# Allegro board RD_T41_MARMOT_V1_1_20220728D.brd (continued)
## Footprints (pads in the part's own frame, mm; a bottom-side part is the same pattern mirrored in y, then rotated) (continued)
QFP16_1D27
  rect 1.4x0.5 smd: 1(-4.6,4.445) 2(-4.6,3.175) 3(-4.6,1.905) 4(-4.6,0.635) 5(-4.6,-0.635) 6(-4.6,-1.905) 7(-4.6,-3.175) 8(-4.6,-4.445) 9(4.6,-4.445) 10(4.6,-3.175) 11(4.6,-1.905) 12(4.6,-0.635) 13(4.6,0.635) 14(4.6,1.905) 15(4.6,3.175) 16(4.6,4.445)
R0402
  rect 0.45x0.55 smd: 1(-0.52,0) 2(0.52,0)
R0603
  rect 0.76x0.76 smd: 1(-0.762,0) 2(0.762,0)
RJ45-LED-1A
  round 3.25 hole 3.25 unplated: (-6.35,5.135) (6.35,5.135)
  rect 1.27x1.27 hole 0.889: 1(3.58,7.675)
  round 1.27 hole 0.889: 2(2.56,9.45) 3(1.54,7.675) 4(0.52,9.45) 5(-0.5,7.675) 6(-1.52,9.45) 7(-2.54,7.675) 8(-3.56,9.45) 11(-6.86,14.27) 12(-4.57,14.27) 13(4.57,14.27) 14(6.86,14.27)
  round 2.286 hole 1.524: 9(-8.13,8.565) 10(8.13,8.565)
SIP2M_2D54
  rect 1.524x1.524 hole 0.889: 1(-1.27,0)
  round 1.524 hole 0.889: 2(1.27,0)
SMB
  rect 2x2.8 smd: 1(2.5,0) 2(-2.5,0)
SOD123
  rect 1.6x1.1 smd: 1(-1.8,0) 2(1.8,0)
SOD323
  rect 0.9x0.9 smd: 1(-1.05,0) 2(1.05,0)
SOP8_1D27_BM8563
  rect 0.4x1.5 smd: 1(-1.905,-2.7) 2(-0.635,-2.7) 3(0.635,-2.7) 4(1.905,-2.7) 5(1.905,2.7) 6(0.635,2.7) 7(-0.635,2.7) 8(-1.905,2.7)
SOT23
  rect 0.8x1.1 smd: 1(-0.95,-1.35) 2(0.95,-1.35) 3(0,1.35)
SOT23-3
  rect 0.8x1.1 smd: 1(0,1.4) 2(-0.95,-1.4) 3(0.95,-1.4)
SOT23-5
  rect 0.6x1.5 smd: 1(-0.95,-1.5) 2(0,-1.5) 3(0.95,-1.5) 4(0.95,1.5) 5(-0.95,1.5)
SOT23-6
  rect 1x0.4 smd: 1(-1.4,0.95) 2(-1.4,0) 3(-1.4,-0.95) 4(1.4,-0.95) 5(1.4,0) 6(1.4,0.95)
SW5_SMD
  oval 2.5x0.85 smd: 1(-3.7,-2.25) 3(-3.7,2.25) 4(3.7,2.25) 5(3.7,-2.25)
  oval 2.2x1 smd: 2(-4,0)
TEST_SMD
  round 1 smd: 1(0,0)
TEST_SMD_0D5
  round 0.5 smd: 1(0,0)
TFCARD
  round 1 hole 1 unplated: (-4.95,-10.6) (3.05,-10.6)
  rect 0.7x1.8 smd: 1(2.25,0.2) 2(1.15,0.2) 3(0.05,0.2) 4(-1.05,0.2) 5(-2.15,0.2) 6(-3.25,0.2) 7(-4.35,0.2) 8(-5.45,0.2) 9(-6.55,0.2)
  rect 1.6x1.4 smd: 10(-8,-0.6) 13(6.85,-0.6)
  rect 1.2x2.2 smd: 11(-7.75,-10.2) 12(7.75,-10.2)
TQFN16_0D5_SGM3124
  rect 0.7x0.23 smd: 1(-1.45,0.75) 2(-1.45,0.25) 3(-1.45,-0.25) 4(-1.45,-0.75) 9(1.45,-0.75) 10(1.45,-0.25) 11(1.45,0.25) 12(1.45,0.75)
  rect 0.23x0.7 smd: 5(-0.75,-1.45) 6(-0.25,-1.45) 7(0.25,-1.45) 8(0.75,-1.45) 13(0.75,1.45) 14(0.25,1.45) 15(-0.25,1.45) 16(-0.75,1.45)
  rect 1.5x1.5 smd: 17(0,0)
VR_3296W
  round 1.5 hole 0.8: 1(-2.5,0) 2(0,0) 3(2.5,0)
WSOP8_1D27
  rect 1.9x0.5 smd: 1(-3.645,1.905) 2(-3.645,0.635) 3(-3.645,-0.635) 4(-3.645,-1.905) 5(3.645,-1.905) 6(3.645,-0.635) 7(3.645,0.635) 8(3.645,1.905)

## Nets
12V_IN: F1.1 J2.3
AVDD33: C188.1 C189.1 R235.2 R236.1 U22.7(AVDD33_1)
AVDDL_REG: C98.1 C99.1 U6.R16(AVDDL_REG)
DVDD1V2OUT: C97.1 C100.1 U6.T14(DVDD1V2OUT)
GND: BAT1.2 BT1.2(-) C2.2 C3.2 C4.2 C5.2 C6.2 C8.2 C9.2 C10.2 C11.2 C12.2 C14.2 C16.2 C17.1 C18.2 C19.2 C21.2 C22.2 C23.2 C25.2 C26.2 C27.2 C28.2 C29.2 C30.2 C31.2 C32.2 C33.2 C34.2 C35.2 C36.2 C37.2 C38.2 C39.2 C40.2 C41.2 C42.2 C43.2 C44.2 C45.2 C46.2 C47.2 C48.2 C49.2 C51.2 C52.2 C53.2 C54.2 C55.2 C56.2 C57.1 C58.1 C59.1 C60.2 C61.2 C62.2 C63.2 C64.2 C67.2 C68.2 C69.1 C70.1 C71.2 C72.2 C73.2 C74.2 C75.2 C76.2 C77.2 C78.2 C79.2 C80.2 C81.2 C82.2 C83.2 C84.2 C85.2 C86.2 C87.2 C88.2 C89.2 C90.2 C91.2 C92.2 C93.2 C94.2 C95.2 C96.2 C97.2 C98.2 C99.2 C100.2 C101.2 C102.2 C103.2 C106.2 C107.2 C108.2 C109.2 C110.2 C111.2 C113.2 C114.2 C115.2 C116.2 C117.2 C118.2 C119.2 C120.2 C121.2 C122.2 C123.2 C124.2 C125.2 C126.2 C127.2 C128.2 C134.2 C135.2 C136.2 C137.2 C138.2 C139.2 C140.2 C141.2 C142.2 C143.2 C146.2 C147.2 C148.2 C149.2 C150.2 C151.2 C152.2 C153.1 C155.2 C156.2 C157.2 C158.2 C159.2 C160.2 C161.2 C162.2 C163.2 C165.2 C166.2 C167.2 C168.2 C169.2 C170.2 C171.2 C172.2 C173.2 C174.2 C175.1 C176.1 C177.1 C178.1 C179.1 C180.2 C181.2 C182.2 C183.2 C184.2 C185.2 C186.1 C187.2 C188.2 C189.2 C190.2 C191.1 C192.1 C193.1 C196.2 C197.2 C198.2 C199.2 C200.2 C201.2 C202.2 C203.2 C204.2 C205.2 C206.2 C207.2 C208.2 C209.1 C210.1 C211.2 C212.1 C214.2 C215.2 D1.1 D2.2(CATHODE) D3.1(ANODE) D4.1(ANODE) D5.1(ANODE) D6.1(ANODE) D7.1(ANODE) D8.1(ANODE) D9.1(ANODE) D10.1(ANODE) D11.1(ANODE) D12.1(ANODE) D13.1(ANODE) D14.1(ANODE) D15.1(ANODE) D16.2 H1.1(A) H2.1(A) H3.1(A) H4.1(A) H5.1(A) H6.1(A) J1.1 J1.2 J7.5(GND1) J7.6(GND2) J7.7(GND3) J7.8(GND4) J7.9(GND5) J7.10(GND6) J7.11(GND7) J9.3(S1) J9.4(S2) J10.3(S1) J10.4(S2) J11.7 J11.10 J11.15 J11.20 J11.27 J11.29 J11.37(S1) J11.38(S2) J12.1 J12.4 J12.7 J12.10 J12.13 J12.16 J12.21 J12.23 J12.27 J12.31(S1) J12.32(S2) J13.3(S1) J13.4(S2) J14.3(S1) J14.4(S2) J15.3(S1) J15.4(S2) J16.6(VSS2) J16.10(GND_2) J16.11(GND_1) J16.12(PAD1) J16.13(PAD2) J17.1 J17.4 J17.8 J17.9 J17.19 J17.32 J17.39 J17.41(S1) J17.42(S2) J18.9(S1) J18.10(S2) J19.9(SH1) J19.10(SH2) J19.12(CON_PIN[11]) J19.14(CON_PIN[13]) J22.1(GND_1) J22.23(DB0) J22.24(DB1) J22.25(DB2) J22.26(DB3) J22.27(DB4) J22.28(DB5) J22.29(DB6) J22.30(DB7) J22.31(DB8) J22.32(DB9) J22.42(GND_2) J22.50(GND_3) J22.51(S1) J22.52(S2) J23.4 J23.13 J23.14 J26.2 J26.5(S1) J26.6(S2) R3.1 R8.1 R9.1 R14.1 R15.1 R20.1 R21.1 R22.1 R29.1 R38.1 R39.3 R40.1 R41.1 R42.1 R59.2 R61.2 R62.2 R89.2 R98.1 R100.2 R102.2 R143.1 R146.1 R149.1 R150.1 R162.1 R170.1 R175.1 R176.2 R177.2 R186.2 R199.1 R217.2 R223.2 R225.1 R226.1 R230.2 R233.2 R248.2 R255.2 R267.1 R276.2 R282.1 R300.1 R308.1 R310.2 R315.2 R317.2 SW1.2 SW1.3 SW1.4 SW2.1 SW2.2 SW2.5 SW4.1 SW4.2 SW4.5 SW5.2 T2.1 T2.2 T2.3 T2.4 T2.5 T2.6 T2.7 T2.8 T2.9 T3.1 T3.2 T3.3 T3.4 T3.5 T3.6 T3.7 T3.8 T3.9 T6.1 T6.2 T6.3 T6.4 T6.5 T6.6 T6.7 T6.8 T6.9 T7.1 T7.2 T7.3 T7.4 T7.5 T7.6 T7.7 T7.8 T7.9 U1.2(GND) U2.2(GND) U3.2(GND) U4.2(GND) U5.2(GND) U6.C9(DDRPLL_VSSA) U6.G5(PLL_AVSS) U6.G6(VSS1) U6.G7(VSS2) U6.G8(VSS3) U6.G9(VSS4) U6.G10(VSS5) U6.G11(VSS6) U6.G12(VSS7) U6.G13(VSS8) U6.J6(VSS9) U6.J7(VSS10) U6.J8(VSS11) U6.J9(VSS12) U6.J10(VSS13) U6.J11(VSS14) U6.J12(VSS15) U6.K6(VSS16) U6.K7(VSS17) U6.K8(VSS18) U6.K9(VSS19) U6.K10(VSS20) U6.K11(VSS21) U6.K12(VSS22) U6.L6(VSS23) U6.L7(VSS24) U6.L8(VSS25) U6.L9(VSS26) U6.L10(VSS27) U6.L11(VSS28) U6.L12(VSS29) U6.M7(VSS30) U6.M8(VSS31) U6.M9(VSS32) U6.M10(VSS33) U6.M11(VSS34) U6.M12(VSS35) U6.M13(VSS36) U6.N5(CSI_VSSA) U6.N12(VSS37) U6.N13(SADC_AGND) U6.P4(CODEC_AVSS) U7.4(GND) U8.1(GND) U9.2(GND) U10.2(GND) U11.7(GND) U12.A6(VSS_1) U12.C4(VSSQ_1) U12.E7(VSS_2) U12.G5(VSS_3) U12.H10(VSS_4) U12.J5(VSS_5) U12.K8(VSS_6) U12.N2(VSSQ_2) U12.N5(VSSQ_3) U12.P4(VSSQ_4) U12.P6(VSSQ_5) U13.5(GND1) U13.6(GND2) U13.7(GND3) U13.8(GND4) U14.5(GND1) U14.6(GND2) U14.7(GND3) U14.8(GND4) U15.5(GND1) U15.6(GND2) U15.7(GND3) U15.8(GND4) U16.5(GND1) U16.6(GND2) U16.7(GND3) U16.8(GND4) U17.2(AVSS1) U17.13(DVSS1) U17.25(DVSS2) U17.30(AVSS2) U17.37(E-PAD) U18.2(GND) U19.7(GND) U20.2(GND) U21.6(GND5) U21.12(MGNDB) U21.18(MGNDA) U21.22(GNDD) U21.33(E-PAD) U22.33(GND) U24.7(PGND) U24.14(GND) U24.17(POWER_PAD) U25.2(GND) U26.2(GND) U27.4(GND) U28.4(GND) Y2.2 Y2.4 Y3.2 Y3.4
VBAT: BAT1.1 C205.1 C211.1 R295.2 R296.1 R303.2 U25.1(VIN) U27.8(VDD)
VBUS_5V: C81.1 C82.1 D4.2(CATHODE) FB8.1 J7.1(VBUS) J8.2
VCC_1V8: C24.1 C27.1 C204.1 J6.1 L5.2 Q1.1(BASE) Q3.2(SOURCE) R13.2 R30.1 R33.1 R36.1 R37.2 U8.3(VCC)
VCC_3V3: C13.1 C18.1 C110.1 C159.1 C160.1 C161.1 C162.1 C163.1 C164.1 C180.1 C181.1 D21.1(ANODE) D22.1(ANODE) FB11.1 FB12.1 FB13.2 FB14.2 FB15.2 FB16.2 J3.1 J17.2 J17.3 J17.5 J17.6 J17.7 J26.1 L2.2 Q2.2(SOURCE) R7.2 R24.2 R73.2 R99.1 R107.2 R128.1 R163.2 R192.2 R198.1 R201.2 R204.1 R215.1 R222.1 R227.1 R232.1 R234.1 R236.2 R249.2 R251.1 R252.1 R257.2 R281.1 R288.2 R289.1 R290.1 R297.1 R301.2 R304.1 R305.2 R306.2 R307.2 R314.1 R316.1 U10.1(VIN) U22.14(DVDD33_1)
VCC_5V: C7.1 C8.1 C9.1 C10.1 C11.1 C14.1 C21.1 C25.1 C80.1 C151.1 C202.1 C203.1 J8.1 J23.1 J23.2 L1.2 R2.1 R4.1 R5.1 R10.1 R11.1 R25.2 R106.2 R122.2 R127.1 R185.2 R189.2 R202.2 R205.2 R207.2 R260.2 TP1.1 U2.4(IN) U3.4(IN) U4.4(IN) U5.4(IN) U9.3(VIN) U18.1(VIN)
VCC_12V: C2.1 C3.1 C4.1 C5.1 D1.2 F1.2 R1.1 TP2.1 U1.5(VIN)
VCC_BAT: BT1.1(+) R35.2
VCC_DDR: C20.1 C23.1 J5.1 L4.2 R12.2
VCCQ_3V3: C115.1 C116.1 FB12.2 R133.1 R134.1 R135.1 R136.1 R137.1 R138.1 R139.1 R140.1 R141.1 R142.2 U12.C6(VCCQ_5) U12.M4(VCCQ_1) U12.N4(VCCQ_2) U12.P3(VCCQ_3) U12.P5(VCCQ_4)
VDD5: C168.1 R207.1 U21.4(VDD5)
VDD_RTC: C59.2 R294.1 U6.L15(VDD_RTC)
VDDIO18: C192.2 R28.1 U6.N11(VDDIO18_1)
VDDIO18_DVP: C95.1 R44.2 U6.K2(VDDIO18_2)
VDDIO33_1: C101.1 R64.1 U6.C4(VDDIO2)
VDDIO33_2: C102.1 C103.1 R63.1 U6.J14(VDDIO1_2) U6.P9(VDDIO1_1)
VDDIO_RTC: C191.2 R323.1 U6.L17(VDDIO_RTC)
VDDMEM: C40.1 C41.1 C42.1 C43.1 C44.1 R17.2 U6.E6(VDDMEM1) U6.E7(VDDMEM2) U6.E8(VDDMEM3) U6.E9(VDDMEM4) U6.E10(VDDMEM5) U6.E11(VDDMEM6) U6.E12(VDDMEM7)
VDDMSC0: C165.1 C166.1 J16.4(VDD) Q2.3(DRAIN) R193.1 R194.1 R195.1 R196.1 R197.1 R199.2
ADC0: C87.1 R35.1 R40.2 TP14.1 U6.P15(SADC_VIN0)
ADC1: C88.1 R36.2 R41.2 TP17.1 U6.R17(SADC_VIN1)
ADC2: C89.1 Q1.2(EMITTER) R42.2 TP15.1 U6.P16(SADC_VIN2)
ADC3: C90.1 R39.2 TP16.1 U6.N15(SADC_VIN3)
ADC_AVDD: C71.1 C72.1 FB7.2 U6.N16(SADC_VREFP) U6.N17(SADC_AVDD)
AK7755_AVDD: C139.1 C140.1 C141.1 C157.1 FB17.2 R183.2 R191.2 U17.21(AVDD1) U17.36(AVDD3) U20.1(VIN)
AK7755_AVDD2: C137.1 C138.1 FB17.1 U17.29(AVDD2)
AK7755_AVDRV: C134.1 U17.24(DVDD/AVDRV)
AK7755_IOVDD: C142.1 C143.1 R163.1 R166.2 R168.1 R169.1 R171.2 R172.2 R174.2 U17.12(TVDD)
AK7755_LDOE: R166.1 U17.23(LDOE)
AK7755_LIN: C130.1 TP50.1
AK7755_PDN: R83.1 R171.1 R173.1
AK7755_VCOM: C135.1 U17.1(VCOM)
BOOTSEL0: D23.2(CATHODE) R297.2 SW4.3 SW4.4 U6.A9(BOOT_SEL0_PC00)
BOOTSEL1: D24.1(ANODE) R300.2 SW5.3 SW5.4 U6.B9(BOOT_SEL1_PC01)
BT656_D0_PD00: J23.5 R254.2
BT656_D1_PD01: J23.6 R256.2
BT656_D2_PD02: J23.7 R259.2
BT656_D3_PD03: J23.8 R263.2
BT656_D4_PD04: J23.9 R264.2
BT656_D5_PD05: J23.10 R268.2
BT656_D6_PD06: J23.11 R270.2
BT656_D7_PD07: J23.12 R272.2
BT656_PCLK_PD08: J23.3 R274.2
CLK_CTRL: R232.2 R233.1 U22.12(RXD[3]/CLK_CTL)
CLKO: TP54.1 U17.9(CLKO)
CODEC_AVDD: C61.1 C62.1 FB6.2 U6.R1(CODEC_AVDD)
CORE_0V8: C29.1 C30.1 C31.1 C32.1 C33.1 C34.1 C35.1 C36.1 C37.1 C38.1 C39.1 J4.2 TP4.1 U6.H5(VDD1) U6.H6(VDD2) U6.H7(VDD3) U6.H8(VDD4) U6.H9(VDD5) U6.H10(VDD6) U6.H11(VDD7) U6.H12(VDD8) U6.H13(VDD9) U6.J5(VDD10) U6.J13(VDD11) U6.K5(VDD12) U6.K13(VDD13) U6.L5(VDD14) U6.M5(VDD15) U6.M6(VDD16) U6.N6(VDD17) U6.N7(VDD18) U6.N8(VDD19) U6.N9(VDD20) U6.N10(VDD21)
CSI_CLKN_DVP_D4: R118.1 R119.1 TP39.1 U6.M2(CSI_CLKN_DVP_D4)
CSI_CLKP_DVP_D5: R116.1 R117.1 TP38.1 U6.L3(CSI_CLKP_DVP_D5)
CSI_DATAN0_DVP_D0: R110.1 R111.1 TP34.1 U6.L2(CSI_DATAN0_DVP_D0)
CSI_DATAN1_DVP_D2: R114.1 R115.1 TP37.1 U6.N1(CSI_DATAN1_DVP_D2)
CSI_DATAP0_DVP_D1: R108.1 R109.1 TP31.1 U6.L1(CSI_DATAP0_DVP_D1)
CSI_DATAP1_DVP_D3: R112.1 R113.1 TP36.1 U6.M3(CSI_DATAP1_DVP_D3)
CSI_VCC08: C91.1 C92.1 FB9.1 U6.N2(CSI_VCCA08)
CSI_VCC18: C93.1 C94.1 FB10.1 U6.K3(CSI_VCCA18)
D_RX: J26.3 R292.1
D_TX: J26.4 R293.1
DC_12V: J1.3 J2.2
DDR_VREF: C50.2 C54.1 R19.1 R22.2 U6.E5(DDR_VREF)
DDRPLL_VCCA: C51.1 C52.1 FB1.2 U6.B8(DDRPLL_VCCA)
DDRVDD: C45.1 C46.1 C47.1 C48.1 C49.1 C50.1 C53.1 R18.2 R19.2 U6.F5(DDRVDD1) U6.F6(DDRVDD2) U6.F7(DDRVDD3) U6.F8(DDRVDD4) U6.F9(DDRVDD5) U6.F10(DDRVDD6) U6.F11(DDRVDD7) U6.F12(DDRVDD8)
DMIC_CLK_PB28: R144.2 R147.2 R153.2 R154.2 R157.2
DMIC_DAT0_PB29: R145.2 R148.2 R321.2
DMIC_DAT1_PB30: R155.2 R158.2 R322.2
DRV_VBUS: R38.2 R55.2 U9.4(EN)
DVP_3V3: J11.1 J11.2 R107.1
DVP_5V: J11.34 J11.35 J11.36 R122.1
DVP_D0: J11.11 R111.2
DVP_D1: J11.12 R109.2
DVP_D2: J11.13 R115.2
DVP_D3: J11.14 R113.2
DVP_D4: J11.16 R119.2
DVP_D5: J11.17 R117.2
DVP_D6: J11.18 U6.H2(SD0_DVP_D6_PA06)
DVP_D7: J11.19 U6.H3(SD1_DVP_D7_PA07)
DVP_D8: J11.21 U6.G1(SD2_DVP_D8_PA08)
DVP_D9: J11.22 U6.G2(SD3_DVP_D9_PA09)
DVP_D10: J11.23 U6.G3(SD4_DVP_D10_PA10)
DVP_D11: J11.24 U6.F2(SD5_DVP_D11_PA11)
DVP_HSYNC: J11.8 TP33.1 U6.J2(CS2_DVP_HSYNC_PA16)
DVP_MCLK_PA15: J11.28 R126.2 TP30.1
DVP_PCLK: J11.26 TP32.1 U6.F3(SA0_DVP_PCLK__PA14)
DVP_VSYNC: J11.9 TP35.1 U6.J3(RD_DVP_VSYNC_PA17)
E_MICBIAS_2V5: C156.1 R182.2 R184.2 U20.5(VOUT)
EC_CLK: R45.2 R65.2 U6.A1(MSC1_CLK_PC02)
EC_CMD: R66.2 R309.1 U6.C3(MSC1_CMD_PC03)
EC_D0: R69.2 R311.1 U6.B2(MSC1_D0_PC04)
EC_D1: R70.2 R318.1 U6.A2(MSC1_D1_PC05)
EC_D2: R71.2 R319.1 U6.C2(MSC1_D2_PC06)
EC_D3: R74.2 R320.1 U6.B1(MSC1_D3_PC07)
EFUSE_AVDD: R324.1 U6.D4(EFUSE_AVDD)
EFUSE_AVDD18: Q3.3(DRAIN) R282.2 R324.2
EFUSE_EN: Q3.1(GATE) R79.1 R281.2
EMMC_3V3: C114.1 C117.1 FB11.2 U12.E6(VCC_1) U12.F5(VCC_2) U12.J10(VCC_3) U12.K9(VCC_4)
EMMC_CLK: C119.1 R65.1 U12.M6(CLK)
EMMC_CMD: R66.1 R141.2 U12.M5(CMD)
EMMC_D0: R69.1 R133.2 U12.A3(DAT0)
EMMC_D1: R70.1 R134.2 U12.A4(DAT1)
EMMC_D2: R71.1 R135.2 U12.A5(DAT2)
EMMC_D3: R74.1 R136.2 U12.B2(DAT3)
EMMC_D4: R137.2 U12.B3(DAT4)
EMMC_D5: R138.2 U12.B4(DAT5)
EMMC_D6: R139.2 U12.B5(DAT6)
EMMC_D7: R140.2 U12.B6(DAT7)
EMMC_DS: TP47.1 U12.H5(DS)
EMMC_RST: C118.1 R76.2 R142.1 U12.K5(RSTN)
EMMC_VDDI: C120.1 U12.C2(VDDI)
EN_DLDO: R60.1 R61.1 U6.U15(EN_DLDO)
EXCLKI: C69.2 R31.2 U6.C1(EXCLK_XIN) Y2.1
EXCLKO: R31.1 R32.2 U6.D2(EXCLK_XOUT)
GMAC_MDC: R49.2 U22.22(MDC)
GMAC_MDIO: R51.2 R215.2 U22.23(MDIO)
GMAC_NRST_PB28: R156.1 R287.2 R298.1
GMAC_PHY_CLK: R47.2 U22.31(XTAL_IN)
GMAC_RXD0: R220.1 U6.U13(GMAC_RXD0_PWM6_PB15)
GMAC_RXD1: R221.1 R222.2 R223.1 U6.R12(GMAC_RXD1_PWM7_PB16)
GMAC_RXDV: R218.1 U6.U9(GMAC_RXDV_PWM3_PB09)
GMAC_TXCLK: R212.1 U6.T12(GMAC_TXCLK_PB06)
GMAC_TXD0: R52.2 U22.16(TXD[0])
GMAC_TXD1: R53.2 U22.17(TXD[1])
GMAC_TXEN: R48.2 U22.20(TXEN)
HPOUTL: C112.2 U6.T1(HPOUTL)
I2C0_MIPI_DVP_SCK: J11.3 J12.20 TP41.1 U6.J4(SD7_SMB0_SCK_PA13)
I2C0_MIPI_DVP_SDA: J11.6 J12.19 TP40.1 U6.J1(SD6_SMB0_SDA_PA12)
I2C1_SCK_CODEC: R88.1 R169.2 U17.18(SCLK/SCL)
I2C1_SCK_RTC: R307.1 U6.C10(SMB1_SCK_UART3_RXD_PB26) U27.6(SCL)
I2C1_SDA_CODEC: R86.1 R168.2 U17.17(SO/SDA)
I2C1_SDA_RTC: R306.1 U6.C11(SMB1_SDA_UART3_TXD_PB25) U27.5(SDA)
I2C2_SID: R174.1 R175.2 U17.20(CSN/CAD/MATSEL)
I2S_DAC_BCLK: R160.1 U6.B4(SSI_SLV_CLK_I2S_DAC_BCLK_PC15)
I2S_DAC_BCLK_PC15: R160.2 U17.8(BICK)
I2S_DAC_LRCK: R159.1 U6.A3(SSI_SLV_CE0_I2S_DAC_LRCK_PC16)
I2S_DAC_LRCK_PC16: R159.2 U17.7(LRCK)
I2S_DAC_MCLK: R77.1 U17.11(XTI)
I2S_SDTI: R161.1 U6.B5(SSI_SLV_DR_I2S_SDTI_PC18)
I2S_SDTI_PC18: R161.2 U17.16(SDOUT1/EEST)
I2S_SDTO: R164.1 U6.B3(SSI_SLV_DT_I2S_SDTO_PC17)
I2S_SDTO_PC17: R164.2 U17.4(SDIN2/JX1)
I_MICBIAS_2V5: C109.1 R93.2 U10.5(VOUT)
IM0: J22.12(IM0) R249.1
IM1: J22.11(IM1) R255.1
IM2: J22.10(IM2) R248.1
INN1: C131.2 U17.33(IN2/INN1/DMCLK1)
INN2: C133.2 U17.31(IN4/INN2/DMCLK2)
INP1: C129.2 U17.34(IN1/INP1/DMDAT1)
INP2: C132.2 U17.32(IN3/INP2/DMDAT2)
IRCUT_IN1: TP62.1 U21.2(IN1)
IRCUT_IN2: TP63.1 U21.3(IN2)
KEY1_PB19: R288.1 SW2.3 SW2.4 TP20.1 U6.D16(MSC1_CMD_PB19)
LED0: R246.1 U6.R13(LED0)
LED1: R299.1 U6.R15(LED1)
LED2: TP65.1 U21.21(LED2)
LED11: TP64.1 U21.20(LED1)
LIN: C130.2 U17.35(LIN)
LR1: R129.2 R143.2 U13.2(L/R)
LR2: R130.2 R146.2 U14.2(L/R)
LR3: R131.2 R149.2 U15.2(L/R)
LR4: R132.2 R150.2 U16.2(L/R)
M_F_A+: J18.7 U21.14(OUTB2)
M_F_A-: J18.8 U21.16(OUTB1)
M_F_B+: J18.1 U21.17(OUTA2)
M_F_B-: J18.2 U21.19(OUTA1)
M_OSCIN: R209.2 U21.24(OSCIN)
M_OSCOUT: R211.2 U21.23(OSCOUT)
M_RSTB: C167.1 R72.2 R204.2 U21.1(RSTB)
M_VD_FZ: R75.2 U21.30(VD_FZ)
M_Z_A+: J18.5 U21.8(OUTD2)
M_Z_A-: J18.6 U21.10(OUTD1)
M_Z_B+: J18.4 U21.11(OUTC2)
M_Z_B-: J18.3 U21.13(OUTC1)
MDI_RN: R219.2 R244.2 U23.1(TD+/RD+)
MDI_RP: R216.2 R242.2 U23.3(TD-/RD-)
MDI_TN: R214.2 R240.2 U23.6(RD+/TD+)
MDI_TP: R213.2 R238.2 U23.8(RD-/TD-)
MDVDD: C173.1 C174.1 R201.1 U21.25(DVDD)
MICBIAS: C85.1 C86.1 R94.2 U6.P3(MICBIAS)
MICN1: C131.1 C144.1 D11.2(CATHODE) J13.1 R176.1 R178.1
MICN2: C133.1 C145.1 D13.2(CATHODE) J14.1 R177.1 R179.1
MICNL: C66.2 C104.1 D7.2(CATHODE) J9.1 R90.1 R313.2
MICP1: C129.1 C144.2 D10.2(CATHODE) J13.2 R178.2 R180.2
MICP2: C132.1 C145.2 D12.2(CATHODE) J14.2 R179.2 R181.2
MICPL: C65.2 C104.2 D6.2(CATHODE) J9.2 R91.2 R97.2
MINNL: C66.1 U6.P2(MICNL)
MINPL: C65.1 U6.N3(MICPL)
MIPI1_2LANE_3V3: J12.30 R128.2
MIPI1_2LANE_5V: J12.28 J12.29 R127.2
MIPI_DVP_IRCUTN_PB18: J11.31 J12.25 TP19.1 U6.E17(MSC1_D1_PB18)
MIPI_DVP_IRCUTP_PB17: J11.32 J12.24 TP18.1 U6.E16(MSC1_D0_PB17)
MIPI_DVP_MCLK: R50.1 R125.1 R126.1 TP42.1
MIPI_DVP_PWDN_PA19: J11.25 J12.26 R229.1 TP44.1
MIPI_DVP_RESET: J11.33 J12.18 TP43.1 U6.E3(SA2_PA18)
MIPI_MCLK_PA15: J12.22 R125.2 TP46.1
MIPI_RX_2LANE_CLKN0: J12.2 R118.2
MIPI_RX_2LANE_CLKP0: J12.3 R116.2
MIPI_RX_2LANE_DN0: J12.5 R110.2
MIPI_RX_2LANE_DN1: J12.8 R114.2
MIPI_RX_2LANE_DP0: J12.6 R108.2
MIPI_RX_2LANE_DP1: J12.9 R112.2
MSC0_CLK_PB04: J16.5(CLK) R43.2 TP61.1
MSC0_CMD_PB05: J16.3(CMD) R197.2 TP60.1 U6.G17(MSC0_CMD_PB05)
MSC0_D0_PB00: J16.7(DAT0) R193.2 TP56.1 U6.H16(MSC0_D0_PB00)
MSC0_D1_PB01: J16.8(DAT1) R194.2 TP57.1 U6.J15(MSC0_D1_PB01)
MSC0_D2_PB02: J16.1(DAT2) R195.2 TP58.1 U6.G15(MSC0_D2_PB02)
MSC0_D3_PB03: J16.2(DAT3) R196.2 TP59.1 U6.G16(MSC0_D3_PB03)
MVCCA: C169.1 C170.1 R202.1 U21.15(MVCCA)
MVCCB: C171.1 C172.1 R205.1 U21.9(MVCCB)
OSC32_XI: C57.2 R23.2 U6.M16(OSC32_XI) Y1.2
OSC32_XO: C58.2 R23.1 U6.M15(OSC32_XO) Y1.1
OUT2_R: TP48.1 U17.26(OUT2)
OUT3_MIXER: TP49.1 U17.27(OUT3)
OUTE1: TP66.1 U21.7(OUTE1)
OUTE2: TP69.1 U21.5(OUTE2)
PHY_ACTA: R224.2 R245.2 R246.2
PHY_LED0: R245.1 R314.2 R315.1 U22.24(LED0/PHYAD[0])
PHY_LED1: R247.1 R316.2 R317.1 U22.25(LED1/PHYAD[1])
PHY_LINKA: R231.2 R247.2 R299.2
PHY_NRST: C96.1 R56.1 R287.1 U6.T13(PHY_RST)
PLL_AVDD18: C55.1 C56.1 FB3.2 U6.D3(PLL_AVDD)
POR_CTRL: R29.2 R30.2 U6.K16(POR_CTL)
PPRST_N: R34.2 U6.L16(PPRST_) U8.2(RESET)
PULSE1: TP67.1 U21.31(PULSE1)
PULSE2: TP68.1 U21.32(PULSE2)
PWRON: TP9.1 U6.K15(PWRON)
RD_N: R244.1 U6.U17(RD_N)
RD_P: R242.1 U6.T17(RD_P)
RMII_MDCK: R49.1 U6.R10(GMAC_MDCK_SMB2_SDA_PB10)
RMII_MDIO: R51.1 U6.T10(GMAC_MDIO_SMB2_SCK_PB11)
RMII_PHY_CLK: R47.1 U6.T9(GMAC_PHY_CLK_PB07)
RMII_TX0: R52.1 U6.R11(GMAC_TXD0_PWM4_PB13)
RMII_TX1: R53.1 U6.T11(GMAC_TXD1_PWM5_PB14)
RMII_TXEN: R48.1 U6.U11(GMAC_TXEN_PWM2_PB08)
RST_OUT: TP7.1 U6.J16(RST_OUT)
RTC_0V8: C208.1 R294.2 TP70.1 U26.5(VOUT)
RTC_1V8: C206.1 C207.1 R285.1 R323.2 U25.5(VOUT) U26.1(VIN)
RTC_IRQ_N: R46.1 R68.2 R305.1 U27.3(INT)
RX+: J19.3(CON_PIN[2]) U23.14(TX-/RX-)
RX-: J19.6(CON_PIN[5]) U23.16(TX+/RX+)
RX_DV: R57.1 U6.P14(RX_DV)
RX_N1: R219.1 U22.6(TRXN1)
RX_P1: R216.1 U22.5(TRXP1)
RXD3: R58.1 R59.1 U6.R14(RXD3)
RXDV: R227.2 R230.1 U22.8(RXDV)
SD0_CD_N_PB27: J16.9(CD) R54.1 R192.1 R237.1
SD_CLK: R43.1 U6.H15(MSC0_CLK_PB04)
SD_PWR_EN_N: R239.1 TP21.1 U6.E15(MSC1_CLK_TCK_PB20)
SDIN1: R162.2 U17.5(SDIN1/JX0)
SDIO_WIFI_CLK_PC02: J17.24 R45.1
SDIO_WIFI_CMD_PC03: J17.34 R309.2
SDIO_WIFI_D0_PC04: J17.23 R311.2
SDIO_WIFI_D1_PC05: J17.35 R318.2
SDIO_WIFI_D2_PC06: J17.33 R319.2
SDIO_WIFI_D3_PC07: J17.36 R320.2
SDIO_WIFI_EN_PC09: J17.16 U6.C6(SMB2_SCK_PC09)
SDOUT2: TP51.1 U17.15(SDOUT2/JX3/MAT0)
SDOUT3: TP52.1 U17.14(SDOUT3/JX2/MAT1)
SFC1_CE: R123.1 R124.1 U6.R7(SFC1_CE_PA29)
SFC1_CLK: R120.1 R121.1 U6.T8(SFC1_CLK_PA22)
SFC1_CS_N: R78.1 R124.2 U28.1(C\S\)
SFC1_DR_IO1: R67.1 R87.1 U6.T7(SFC1_DR_IO1_PA21)
SFC1_DT_IO0: R82.1 R85.1 U6.R8(SFC1_DT_IO0_PA20)
SFC1_HD_IO3: R75.1 R165.1 U6.R9(SFC1_HOLD_IO3_PA31)
SFC1_SCLK: R121.2 U28.6(SCLK)
SFC1_SIO0: R85.2 U28.5(SI/SIO0)
SFC1_SIO1: R87.2 U28.2(SO/SIO1)
SFC1_SIO2: R167.2 U28.3(W\P\/SIO2)
SFC1_SIO3: R165.2 U28.7(R\E\S\E\T\/SIO3)
SFC1_WP_IO2: R72.1 R167.1 U6.U7(SFC1_WP_IO2_PA30)
SFC_CS_N: R26.1 U6.T4(SFC0_CE_PA28) U7.1(C\S\)
SFC_SCLK: U6.R6(SFC0_CLK_PA27) U7.6(SCLK)
SFC_SIO0: U6.U5(SFC0_DT_IO0_PA23) U7.5(SI/SIO0)
SFC_SIO1: U6.R5(SFC0_DR_IO1_PA24) U7.2(SO/SIO1)
SFC_SIO2: U6.T5(SFC0_WP_IO2_PA26) U7.3(W\P\/SIO2)
SFC_SIO3: U6.T6(SFC0_HOLD_IO3_PA25) U7.7(R\E\S\E\T\/SIO3)
SLCD_BLEN: R81.1 R276.1 U24.15(EN1) U24.16(EN2)
SLCD_BT656_D0: R253.1 R254.1 U6.A15(SLCD_D0_UART3_TXD_PD00)
SLCD_BT656_D1: R250.1 R256.1 U6.B15(SLCD_D1_UART3_RXD_PD01)
SLCD_BT656_D2: R258.1 R259.1 U6.A16(SLCD_D2_UART4_TXD_PD02)
SLCD_BT656_D3: R261.1 R263.1 U6.C15(SLCD_D3_UART4_RXD_PD03)
SLCD_BT656_D4: R262.1 R264.1 U6.A17(SLCD_D4_UART5_TXD_PD04)
SLCD_BT656_D5: R266.1 R268.1 U6.B16(SLCD_D5_UART5_RXD_PD05)
SLCD_BT656_D6: R269.1 R270.1 U6.B17(SLCD_D6_SMB1_SDA_PD06)
SLCD_BT656_D7: R271.1 R272.1 U6.C16(SLCD_D7_SMB1_SCK_PD07)
SLCD_CS: R277.1 TP27.1 U6.B13(SLCD_CS_PWM5_PD10)
SLCD_CS_PD10: J22.14(CS) R277.2
SLCD_D0_PD00: J22.33(DB10) R253.2
SLCD_D1_PD01: J22.34(DB11) R250.2
SLCD_D2_PD02: J22.35(DB12) R258.2
SLCD_D3_PD03: J22.36(DB13) R261.2
SLCD_D4_PD04: J22.37(DB14) R262.2
SLCD_D5_PD05: J22.38(DB15) R266.2
SLCD_D6_PD06: J22.39(DB16) R269.2
SLCD_D7_PD07: J22.40(DB17) R271.2
SLCD_DC: R278.1 TP28.1 U6.C13(SLCD_DC_PWM6_PD11)
SLCD_DC_PD11: J22.15(RS_SPI-RS) R278.2
SLCD_IOVDD: C198.1 C200.1 J22.6(IOVCC_1) J22.7(IOVCC_2) R251.2
SLCD_LEDA: C201.1 J22.43(LEDA) U24.8(VOUT)
SLCD_LEDK: J22.44(LEDK1) J22.45(LEDK2) J22.46(LEDK3) J22.47(LEDK4) J22.48(LEDK5) J22.49(LEDK6) R265.2 U24.5(D2) U24.6(D1)
SLCD_RDY: R279.1 TP29.1 U6.C14(SLCD_RDY_PWM7_PD12)
SLCD_RDY_PD12: J22.17(RD) R257.1 R279.2
SLCD_RST_PD09: J22.13(RESET) R275.2
SLCD_TE: R275.1 TP26.1 U6.A13(SLCD_TE_PWM4_PD09)
SLCD_VCI: C197.1 C199.1 J22.8(VCI_1) J22.9(VCI_2) R252.2
SLCD_WR_BT656_PCLK: R273.1 R274.1 U6.B14(SLCD_WR_PD08)
SLCD_WR_PD08: J22.16(WR_SPI-SCL) R273.2
SOC_0V8: C15.2 C16.1 C17.2 J4.1 L3.2 R6.2 R325.1 R330.2
SOC_1V8: J6.2 R27.2 R28.2 R44.1 R80.1 R84.1 R326.1 R328.1 R329.1 R331.2 TP6.1
SOC_3V3: J3.2 R16.1 R56.2 R57.2 R58.2 R60.2 R63.2 R64.2 R327.1 TP3.1
SOC_DDR: J5.2 R17.1 R18.1 TP5.1
SPEAK_EN_PB31: R103.1 R187.1 U6.B10(GPIO_PB31)
SPI1_CLK: R120.2 R206.1
SPI1_CLK_PA22: R206.2 U21.26(SCK)
SPI1_CS: R123.2 R208.1
SPI1_CS_PA29: R208.2 U21.27(CS)
SPI1_DR: R67.2 R203.1
SPI1_DR_PA21: R203.2 U21.28(SOUT)
SPI1_DT: R82.2 R200.1
SPI1_DT_PA20: R200.2 U21.29(SIN)
SPK_OUTL: C154.1 U17.28(OUT1)
SPKOUT_N: D8.2(CATHODE) J10.1 R101.1 U11.8(VO-)
SPKOUT_P: D9.2(CATHODE) J10.2 R95.1 U11.5(VO+)
STO: TP55.1 U17.6(STO/RDY)
TD_N: R240.1 U6.U16(TD_N)
TD_P: R238.1 U6.T16(TD_P)
TEST_TE: TP8.1 U6.L13(TEST_TE)
TX+: J19.1(CON_PIN[0]) U23.9(RX-/TX-)
TX-: J19.2(CON_PIN[1]) U23.11(RX+/TX+)
TX_N0: R214.1 U22.4(TRXN0)
TX_P0: R213.1 U22.3(TRXP0)
U0_RTS_PB21: R76.1 TP22.1 U6.C17(MSC1_D2_TMS_PB21)
U0_TXD_PB22: R68.1 TP23.1 U6.D15(MSC1_D3_PB22)
UART1_RXD_PB24: R289.2 R292.2 U6.F16(UART1_RXD_PB24)
UART1_TXD_PB23: R290.2 R293.2 U6.F15(UART1_TXD_PB23)
USB_AVD08: C73.1 C74.1 FB4.2 U6.R4(USB_AVD08)
USB_AVD18: C76.1 C77.1 FB2.2 U6.T3(USB_AVD18)
USB_AVD33: C78.1 C79.1 FB5.2 U6.R3(USB_AVD33)
USB_DM: R151.1 U6.U1(USB0PN)
USB_DP: R152.1 U6.T2(USB0PP)
USB_ID: R27.1 U6.U2(USB0ID)
USB_VBUS: R25.1 R310.1 U6.U3(VBUS)
VCM: C67.1 C68.1 U6.R2(VCM)
WIFI_WAKE_HOST: TP45.1 U6.B6(SMB2_SDA_PC08)
WKUP_PD31: TP11.1 U6.J17(WKUP_PD31)
XTO: TP53.1 U17.10(XTO)
N14970173: C7.2 R2.2 R3.2 U1.3(FB)
N14970293: C1.2 L1.1 U1.6(LX)
N15664622: C6.1 R1.2 U1.4(EN)
N16749111: C60.1 C64.1 R24.1 R26.2 U7.8(VCC)
N16751575: C70.2 R32.1 Y2.3
N16753264: C75.1 R33.2 R34.1 SW1.1 SW1.5
N16757380: R37.1 R39.1
N16760505: D3.2(CATHODE) J7.2(D-) R151.2 TP13.1
N16760513: D5.2(CATHODE) J7.3(D+) R152.2 TP12.1
N16760739: C83.1 C84.1 FB8.2 U9.1(VOUT0) U9.5(VOUT1)
N16771643: C105.2 R91.1 R92.2
N16771875: C106.1 R92.1 R93.1 R94.1
N16774062: C113.1 R106.1 U11.6(VDD)
N16774094: R105.1 U11.4(-IN)
N16774098: C112.1 R105.2
N16774118: C111.1 R104.2
N16774180: R102.1 R103.2 U11.1(/SD)
N16774192: R104.1 U11.3(+IN)
N16775243: R99.2 U10.3(STBY)
N16779173: R50.2 U6.E1(SA1_DVP_MCLK_PA15)
N16859821: R170.2 U17.19(SI/EXTEEP)
N16859918: R172.1 U17.3(I2CSEL)
N16859920: C136.1 R173.2 U17.22(PDN)
N16861141: R144.1 U13.3(CLK)
N16861143: R145.1 U13.4(DATA)
N16861165: R147.1 U14.3(CLK)
N16861167: R148.1 U14.4(DATA)
N16861179: C123.1 C124.1 FB14.1 R130.1 U14.1(VDD)
N16861294: R154.1 U15.3(CLK)
N16861296: R155.1 U15.4(DATA)
N16861324: C125.1 C126.1 FB15.1 R131.1 U15.1(VDD)
N16861434: R157.1 U16.3(CLK)
N16861436: R158.1 U16.4(DATA)
N16861448: C127.1 C128.1 FB16.1 R132.1 U16.1(VDD)
N16861556: C121.1 C122.1 FB13.1 R129.1 U13.1(VDD)
N16862955: C146.1 C147.1 R180.1 R184.1
N16863107: C150.1 R183.1 U18.5(VOUT)
N16863121: C152.1 R185.1 U18.3(STBY)
N16863211: C158.1 R191.1 U20.3(STBY)
N16871764: C148.1 C149.1 R181.1 R182.1
N16876325: D14.2(CATHODE) J15.2 U19.5(VO+)
N16876337: D15.2(CATHODE) J15.1 U19.8(VO-)
N16876351: C155.1 R189.1 U19.6(VDD)
N16876358: R190.1 U19.4(-IN)
N16876368: C154.2 R190.2
N16876378: C153.2 R188.2
N16876406: R186.1 R187.2 U19.1(/SD)
N16876412: R188.1 U19.3(+IN)
N16900408: C164.2 Q2.1(GATE) R198.2 R237.2 R239.2
N16904771: C175.2 R209.1 R210.2 Y3.3
N16904783: C176.2 R210.1 R211.1 Y3.1
N17093743: D2.1(ANODE) R16.2
N17110008: D23.1(ANODE) R304.2
N17238740: C105.1 R89.1 R90.2
N17269254: R301.1 SW5.1 SW5.5
N17275101: D24.2(CATHODE) R308.2
N17289134: C12.1 R4.2 U2.1(EN)
N17289227: C13.2 R7.1 R8.2 U2.5(FB)
N17289243: L2.1 U2.3(LX)
N17291669: C22.1 R10.2 U4.1(EN)
N17291730: C20.2 R12.1 R14.2 U4.5(FB)
N17291736: L4.1 U4.3(LX)
N17297008: C26.1 R11.2 U5.1(EN)
N17297010: C24.2 R13.1 R15.2 U5.5(FB)
N17297090: L5.1 U5.3(LX)
N17502278: R20.2 U6.F13(DDR_ZQ)
N17525430: C63.1 FB6.1 R328.2
N17525778: FB4.1 R325.2
N17525816: FB2.1 R326.2
N17525850: FB5.1 R327.2
N17560999: FB7.1 R329.2
N17611755: C15.1 R6.1 R9.2 U3.5(FB)
N17611809: C19.1 R5.2 U3.1(EN)
N17611937: L3.1 U3.3(LX)
N17639490: R267.2 U24.1(ISET)
N17639502: C194.2 U24.12(C2-)
N17639539: C195.1 U24.10(C1+)
N17639549: C194.1 U24.9(C2+)
N17639559: C195.2 U24.11(C1-)
N17639566: C196.1 R260.1 U24.13(VIN)
N17641417: D21.2(CATHODE) R295.1
N17641433: R296.2 U25.3(EN)
N17672752: TP10.1 U6.D14(TRST_)
N17678928: R153.1 R156.2 U6.A11(DMIC_CLK_SMB2_SCK_PB28)
N17679213: R54.2 R55.1 U6.B11(DRV_VBUS_SMB2_SDA_PB27)
N17680383: R62.1 U6.T15(RBIAS)
N17689049: R77.2 U6.C5(I2S_DAC_MCLK_PC11)
N17689055: R81.2 U6.B7(I2S_ADC_BCLK_PC13)
N17689058: R83.2 U6.C7(I2S_ADC_LRCK_PC14)
N17690769: R86.2 U6.A7(SMB1_SDA_PC19)
N17690856: R88.2 U6.C8(SMB1_SCK_PC20)
N17700250: D22.2(CATHODE) R303.1
N17700350: C209.2 U27.1(OSCI) Y4.2
N17700378: C210.2 U27.2(OSC0) Y4.1
N17705583: C187.1 R234.2 R298.2 U22.21(RESET_N)
N17705597: R218.2 U22.26(CRS/CRS_DV)
N17705611: R220.2 U22.9(RXD[0])
N17705613: R221.2 U22.10(RXD[1])
N17705750: R235.1 U22.30(NC)
N17705784: R226.2 U22.32(XTAL_OUT)
N17705826: R212.2 U22.15(TXC)
N17705884: C184.1 C185.1 U22.2(AVDDL_REG)
N17705928: C182.1 C183.1 U22.29(DVDDL_REG)
N17706002: R225.2 U22.28(RXER)
N17706200: R217.1 U22.1(PBIAS)
N17706222: C179.2 U23.7(CT2)
N17706227: D16.1 R228.2 U23.10(CT3) U23.13(MCT) U23.15(CT4)
N17706250: C178.2 U23.5(CT)
N17706256: C177.2 U23.2(CT1)
N17706349: J19.11(CON_PIN[10]) R224.1
N17706354: J19.13(CON_PIN[12]) R231.1
N17706406: C186.2 R228.1
N17728418: R21.2 U6.D9(RZQ)
N17861413: C214.1 U25.4(BP/FB)
N17864164: R285.2 U26.3(EN)
N17864213: C215.1 U26.4(BP/FB)
N17919056: C107.1 R95.2 R96.1
N17919062: C212.2 R101.2 R312.1
N17919066: C108.1 R96.2 R97.1 R98.2
N17919088: C193.2 R100.1 R312.2 R313.1
N17957644: R46.2 R321.1 U6.B12(DMIC_DAT0_UART4_TXD_PB29)
N17957722: R322.1 U6.C12(DMIC_DAT1_UART4_RXD_PB30)
N17960615: R229.2 U6.E2(WAIT_PA19)
N17962213: R79.2 U6.A5(I2S_ADC_MCLK_PC12)
N17974466: FB1.1 R80.2
N17976184: FB3.1 R84.2
N17978297: FB9.2 R330.1
N17978317: FB10.2 R331.1
N18062125: C28.1 C190.1 R73.1 R78.2 U28.8(VCC)
N149702450: C1.1 U1.1(BS)
N176395273: R265.1 U24.4(D3)

Pads without a net: J2 1; J7 4; J11 4 5 30; J12 11 12 14 15 17; J17 10 11 12 13 14 15 17 18 20 21 22 25 26 27 28 29 30 31 37 38 40; J19 4 5 7 8; J22 2 3 4 5 18 19 20 21 22 41; U10 4; U11 2; U12 A1 A2 A7 A8 A9 A10 A11 A12 A13 A14 B1 B7 B8 B9 B10 B11 B12 B13 B14 C1 C3 C5 C7 C8 C9 C10 C11 C12 C13 C14 D1 D2 D3 D4 D12 D13 D14 E1 E2 E3 E5 E8 E9 E10 E12 E13 E14 F1 F2 F3 F10 F12 F13 F14 G1 G2 G3 G10 G12 G13 G14 H1 H2 H3 H12 H13 H14 J1 J2 J3 J12 J13 J14 K1 K2 K3 K6 K7 K10 K12 K13 K14 L1 L2 L3 L12 L13 L14 M1 M2 M3 M7 M8 M9 M10 M11 M12 M13 M14 N1 N3 N6 N7 N8 N9 N10 N11 N12 N13 N14 P1 P2 P7 P8 P9 P10 P11 P12 P13 P14; U18 4; U19 2; U20 4; U22 11 13 18 19 27; U23 4 12; U24 2 3; U27 7

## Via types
v1: diameter 0.406, hole 0.203, TOP to BOTTOM, 1909 vias

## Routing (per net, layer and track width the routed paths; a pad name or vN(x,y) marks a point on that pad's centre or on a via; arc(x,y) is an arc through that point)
AVDD33: length 11.9
  TOP w0.254: U22.7 v1(85.17,16.7)
  TOP w0.381: R235.2 82.72,9.89 v1(82.49,9.66)
  BOTTOM w0.381: C189.1 84.5,16.22 C188.1 84.78,15.35 85.73,14.4 85.73,13.25 82.49,10 v1(82.49,9.66) ; C189.1 84.63,17.03 R236.1 ; C189.1 84.83,16.36 v1(85.17,16.7)
AVDDL_REG: length 2.3
  TOP w0.254: U6.R16 v1(68.26,44.26)
  BOTTOM w0.254: C99.1 68.86,43.6 C98.1 68.86,43.66 v1(68.26,44.26)
DVDD1V2OUT: length 3.3
  TOP w0.254: U6.T14 v1(66.96,43.61)
  BOTTOM w0.254: v1(66.96,43.61) 67.08,43.49 C97.1 67.97,41.69 C100.1
GND: length 475.9
  TOP w0.081: 53.27,75.24 53.04,75.01 52.57,75.01 U12.N2 52.56,75.51 53.11,75.51 53.27,75.36
  TOP w0.089: 53.27,75.36 v1(53.33,75.3) 53.27,75.24
  TOP w0.102: 72.1,45 71.85,45.25 v1(69.64,45.25)
  TOP w0.203: v1(49.65,71.67) 49.81,71.51 U12.E7 ; U12.C4 v1(50.86,70.72) ; U12.P4 v1(51.31,76.17) ; U12.N5 U12.P6 v1(49.85,76.23) ; 58.04,37.26 59.35,38.57 59.35,41.67 59.62,41.94 v1(59.62,42.35) ; U12.A6 50.31,68.84 v1(50.1,68.62) ; v1(50.35,72.39) 50.48,72.26 U12.G5 ; 57.88,38.78 57.88,41.86 58.25,42.23 v1(58.25,42.27) ; U12.J5 v1(50.35,73.26)
  TOP w0.249: U21.12 v1(63.31,8.32)
  TOP w0.254: J23.14 117.2,99.99 ; J23.14 116.14,101.05 ; J23.14 116.14,98.94 ; J23.14 115.08,99.99 ; v1(33.38,35.52) J12.27 v1(35.33,35.52) ; v1(30.25,5.81) D9.1 v1(29.49,6.36) ; 27.17,1.8 J10.3 ; J10.3 28.38,3.26 ; J10.3 29.58,1.8 ; v1(106.91,67.44) C196.2 108,67.74 U24.14 110.15,67.74 v1(110.4,67.49) 110.65,67.74 U24.7 v1(112.55,67.74) ; U6.G12 v1(65.66,50.11) U6.G13 ; J19.9 116.46,4.68 ; 34.07,1.8 J10.4 ; J10.4 35.28,3.26 ; J10.4 36.48,1.8 ; 66.09,99.2 J14.4 ; J14.4 67.29,100.66 ; J14.4 64.88,100.66 ; J14.4 66.09,102.11 ; v1(33.34,5.83) D8.1 v1(34.09,6.36) ; J7.6 46.84,2.18 ; J7.6 45.84,3.48 ; J7.6 45.84,0.87 ; J7.6 44.83,2.18 ; v1(30.69,90.72) U1.2 v1(30.69,88.82) ; v1(66.72,13.86) 67.11,14.25 v1(69.27,14.25) 69.97,14.95 69.97,15.64 70.36,16.03 v1(71.11,16.03) C175.1 71.71,14.39 Y3.2 v1(72.95,13.15) 72.95,10.6 72.55,10.2 v1(71.29,10.2) C176.1 70.52,10.97 Y3.4 70.26,11.92 v1(69.59,11.92) 67.06,11.92 v1(66.71,12.27) U21.22 ; R223.2 79.14,20.71 v1(78.85,21) ; D12.1 v1(60.46,98.29) ; U12.H10 48.26,72.76 v1(47.82,72.32) ; 49.73,99.12 J13.3 ; J13.3 50.94,100.58 ; J13.3 48.53,100.58 ; J13.3 49.73,102.03 ; 122.54,50.63 J26.6 ; J26.6 123.84,49.57 ; J26.6 123.84,51.68 ; J15.3 78.25,103.45 ; J15.3 75.84,103.45 ; J15.3 77.04,102 ; U6.L11 v1(64.36,46.86) U6.L10 ; 69.56,1.54 J18.10 71.97,1.54 ; R186.2 v1(71.21,90.77) ; U17.2 v1(59.62,82.88) ; J16.12 120.69,49.46 ; J16.12 120.69,47.75 ; J16.12 122.05,48.61 ; J16.12 119.34,48.61 ; J22.50 v1(119.56,69.95) ; C126.2 v1(105.82,89.45) ; R3.1 v1(30.03,88.18) ; J18.9 57.47,1.54 ; J18.9 56.27,3 ; J18.9 55.06,1.54 ; v1(35.33,42.52) J12.13 v1(33.38,42.52) ; R248.2 113.41,89.36 R255.2 v1(111.02,89.36) ; R102.2 v1(33.09,16.48) ; v1(87.41,5.97) 87.41,5.74 87.67,5.49 U14.8 ; U6.J8 v1(63.06,48.81) U6.J9 ; J15.4 71.35,103.45 ; J15.4 70.14,102 ; J15.4 68.94,103.45 ; U17.30 64.59,85.2 v1(64.45,85.35) ; v1(59.81,44.91) U6.P4 v1(60.46,45.56) U6.N5 ; 119.34,33.11 J16.11 ; J16.11 120.69,32.25 ; J16.11 122.05,33.11 ; J16.11 120.69,33.96 ; C106.2 v1(15.39,7.59) ; C106.2 v1(14.14,7.59) ; C106.2 v1(14.77,6.96) ; v1(73.35,97.91) U19.7 v1(73.35,95.71) ; U6.G8 v1(63.06,50.11) U6.G9 ; U6.M12 v1(65.66,46.21) U6.M13 ; U6.G5 v1(60.46,50.11) ; v1(33.38,38.52) J12.21 v1(35.33,38.52) ; D13.1 v1(64.81,98.3) ; U15.5 104.65,89.87 v1(105.16,89.36) ; 116.14,101.48 J23.13 ; J23.13 116.14,103.59 ; J23.13 115.08,102.53 ; J23.13 117.2,102.53 ; 120.01,96.1 J22.51 ; J22.51 122.72,96.1 ; J22.51 121.36,97.25 ; J22.51 121.36,94.94 ; C123.2 v1(85.67,4.49) ; 55.43,100.58 J13.4 ; J13.4 56.63,102.03 ; J13.4 57.84,100.58 ; J13.4 56.63,99.12 ; Y2.4 53.85,51.38 v1(54.47,51.38) ; 14.28,1.82 J9.3 ; J9.3 16.69,1.82 ; J9.3 15.48,3.28 ; v1(2.72,14.76) 3.19,14.28 U13.6 ; J26.5 123.84,57.68 ; J26.5 123.84,55.57 ; J26.5 122.54,56.63 ; U16.8 16.04,60.31 15.81,60.09 v1(15.81,59.67) ; U6.J12 v1(65.66,48.81) ; U6.L6 v1(61.76,46.86) U6.L7 ; U6.K7 v1(61.76,47.51) U6.K6 ; Y2.2 51.68,53.76 v1(51.37,54.08) C69.1 52.32,55.03 53.14,55.03 53.46,54.7 v1(53.46,54.16) 53.93,54.16 54.23,53.86 56.18,53.86 v1(56.44,53.6) ; U17.13 v1(63.09,77.4) ; U6.K11 v1(64.36,47.51) U6.K10 ; U14.7 90.28,3.69 v1(90.71,3.26) ; U8.1 v1(18.78,66.46) ; v1(28.59,77.53) U5.2 v1(26.38,77.53) ; 59.19,99.2 J14.3 ; J14.3 57.98,100.66 ; J14.3 59.19,102.11 ; J14.3 60.39,100.66 ; v1(86.51,5.17) 86.83,4.85 U14.5 ; C87.2 v1(98.29,32.48) ; U6.L12 v1(65.66,47.51) U6.K12 ; C201.2 113.44,67.55 v1(113.79,67.9) ; U15.8 102.12,88.87 101.85,88.6 v1(101.85,88.31) ; R170.1 70.07,78.65 R175.1 ; J22.30 v1(116.87,79.95) ; v1(49.02,74.31) 49.31,74.01 U12.K8 ; C153.1 73.34,87.19 v1(73.08,87.45) ; U6.G6 v1(61.76,50.11) U6.G7 ; v1(29.13,68.52) U2.2 v1(26.86,68.52) ; R300.1 v1(11.84,78.99) ; v1(33.38,45.52) J12.7 v1(35.33,45.52) ; U6.N13 v1(65.66,45.56) U6.N12 ; J19.12 110.83,11.18 112.97,9.03 112.97,5.58 ; J19.10 116.46,25.42 116.97,25.93 ; v1(75.13,99.6) D14.1 v1(75.86,99) ; D11.1 v1(55.45,98.29) ; U6.M9 v1(63.06,46.21) U6.M8 ; J22.23 v1(119.56,83.45) ; J7.7 54.09,2.18 ; J7.7 53.09,0.87 ; J7.7 53.09,3.48 ; J7.7 52.08,2.18 ; v1(106.95,30.75) R41.1 107.61,30.74 C88.2 ; 121.36,67.14 J22.52 ; J22.52 120.01,68.3 ; J22.52 122.72,68.3 ; J22.52 121.36,69.45 ; 112.05,32.86 J16.10 110.14,32.86 ; U6.G11 v1(64.36,50.11) U6.G10 ; v1(38.03,41.02) J12.16 v1(36.08,41.02) ; R8.1 v1(24.88,65) ; J9.4 23.59,1.82 ; J9.4 21.18,1.82 ; J9.4 22.38,3.28 ; J19.14 110.75,25.67 110.76,25.68 ; v1(35.33,37.52) J12.23 v1(33.38,37.52) ; v1(5.33,15.42) 4.97,15.06 U13.5 ; v1(29.32,73.68) C27.2 v1(30.1,73) ; v1(116.87,73.95) J22.42 v1(119.56,73.95) ; U6.L9 v1(63.06,46.86) U6.L8 ; U6.C9 v1(63.06,52.71) ; U13.8 5.64,14.22 5.9,14.48 v1(6.19,14.48) ; U6.M7 v1(61.76,46.21) ; C125.2 v1(106.75,89.45) ; v1(71.36,39.75) 71.36,39.37 R61.2 ; 72.1,45 72.76,44.35 v1(73.13,44.35) 73.34,44.14 73.34,43.68 74,43.03 v1(74.47,43.03) 74.86,43.42 v1(76.76,43.42) 76.97,43.63 v1(76.97,44.53) ; J22.25 v1(119.56,82.45) ; v1(21.75,76.96) C25.2 v1(21.98,76.35) ; v1(5.39,11.26) 5.04,11.61 U13.7 ; J17.39 v1(96.39,62.56) ; 110.14,47.71 J16.13 ; J16.13 111.09,46.65 ; J16.13 112.05,47.71 ; J16.13 111.09,48.76 ; J22.1 v1(116.86,94.45) ; J22.31 v1(119.56,79.45) ; v1(35.31,48.52) J12.1 v1(33.38,48.52) ; J22.28 v1(116.87,80.95) ; R42.1 v1(94.24,32.81) ; R40.1 v1(97.32,32.49) ; D3.1 v1(48.53,8.52) ; D5.1 v1(49.74,8.52) ; R225.1 v1(81.8,9.69) ; R276.2 v1(108.41,65.02) ; U6.J10 v1(64.36,48.81) U6.J11 ; C167.2 57.74,14.28 v1(57.41,14.61) ; U6.J6 v1(61.76,48.81) U6.J7 ; C124.2 v1(84.74,4.49) ; v1(69.23,40.55) 69.29,40.49 C96.2 ; v1(32.06,9.77) U11.7 v1(32.06,7.51) ; J22.29 v1(119.56,80.45) ; J17.1 v1(115.39,62.56) ; 36.08,44.02 J12.10 v1(38.03,44.02) ; J22.32 v1(116.87,78.95) ; D10.1 v1(50.95,98.28) ; R15.1 24.53,73.98 ; U25.2 87.88,61.06 v1(87.61,61.33) v1(88.14,61.33) 88.14,61.79 C205.2 ; U6.M11 v1(64.36,46.21) U6.M10 ; C111.2 v1(31.57,18.4) ; C155.2 v1(76.42,93.45) ; 37.06,47.02 v1(36.08,47.02) ; J22.27 v1(119.56,81.45) ; v1(111.52,37.61) J16.6 v1(109.07,37.61) ; R226.1 v1(83.71,9.72) ; U6.K9 v1(63.06,47.51) U6.K8 ; v1(72.11,99.6) D15.1 v1(71.38,98.99) ; J22.26 v1(116.87,81.95) ; J7.5 v1(50.76,5.8) ; J22.24 v1(116.87,82.95) ; J17.9 v1(111.39,62.56) ; C89.2 v1(91.93,32.81) ; C26.2 v1(26.72,80.47)
  TOP w0.305: C122.2 v1(4.87,17.14) ; D11.1 v1(54.76,98.87) ; D12.1 v1(61.14,98.88) ; C148.2 v1(61.52,97.29) ; C147.2 v1(50.57,97.82) ; D10.1 v1(51.63,98.87) ; C149.2 v1(59.99,97.89) ; R177.2 v1(64.07,95.99) ; D13.1 v1(64.13,98.89) ; R176.2 v1(54.67,95.92) ; C146.2 v1(52.08,97.23) ; C121.2 v1(4.87,16.2)
  TOP w0.33: D6.1 v1(16.78,6.24) ; v1(111.28,57.83) 111.89,58.43 J17.8 ; R89.2 v1(20.53,7.57) ; D7.1 v1(21.06,6.25) ; J17.4 v1(113.89,58.01) ; R170.1 v1(70.08,78.01)
  TOP w0.381: C157.2 v1(57.73,87.45) ; v1(50.43,88.15) C156.2 v1(51.07,87.5) ; v1(34.48,12.75) C113.2 v1(33.73,11.94) ; J26.2 v1(118.39,53.13) ; v1(54.06,87.37) U20.2 v1(56.32,87.37)
  L2_GND w0.254: 116.14,101.48 J23.13 ; J23.13 116.14,103.59 ; J23.13 115.08,102.53 ; J23.13 117.2,102.53 ; 44.83,2.18 J7.6 ; J7.6 46.84,2.18 ; J7.6 45.84,3.48 ; J7.6 45.84,0.87 ; J7.7 53.09,3.48 ; J7.7 54.09,2.18 ; J7.7 53.09,0.87 ; J7.7 52.08,2.18 ; J23.14 117.2,99.99 ; J23.14 116.14,98.94 ; J23.14 115.08,99.99 ; J23.14 116.14,101.05
  L3_PWR w0.254: J7.6 46.84,2.18 ; J7.6 45.84,0.87 ; J7.6 44.83,2.18 ; J7.6 45.84,3.48 ; 116.14,98.94 J23.14 ; J23.14 115.08,99.99 ; J23.14 116.14,101.05 ; J23.14 117.2,99.99 ; J23.13 116.14,103.59 ; J23.13 116.14,101.48 ; J23.13 117.2,102.53 ; J23.13 115.08,102.53 ; 53.09,0.87 J7.7 ; J7.7 53.09,3.48 ; J7.7 52.08,2.18 ; J7.7 54.09,2.18
  BOTTOM w0.102: v1(94.94,57.89) 92.49,57.89
  BOTTOM w0.254: v1(44.54,11.3) C80.2 v1(43.17,11.3) ; v1(43.16,10.49) R38.1 v1(44.54,10.49) ; R100.2 v1(24.74,10.51) ; C72.2 70.1,44.8 v1(69.64,45.25) 69.56,45.16 C59.1 ; C72.2 70.47,44.62 v1(70.47,43.66) ; C72.2 71.21,44.8 C71.2 ; C118.2 52.79,75.84 v1(53.33,75.3) ; C114.2 v1(53.27,71.71) ; C23.2 v1(83.68,61.85) ; C23.2 v1(84.38,62.5) ; C23.2 v1(82.97,62.5) ; 115.08,99.99 J23.14 ; J23.14 117.2,99.99 ; J23.14 116.14,101.05 ; J23.14 116.14,98.94 ; J7.6 45.84,3.48 ; J7.6 44.83,2.18 ; J7.6 45.84,0.87 ; J7.6 46.84,2.18 ; U27.4 77.2,71.3 v1(77.64,71.75) ; v1(90.52,65.67) C21.2 v1(91.26,64.79) ; C207.2 91.27,51.64 v1(91.31,51.6) ; v1(15.52,15.2) U10.2 v1(15.52,17.49) 15.52,18.02 C110.2 ; v1(68.26,46.86) 68.58,47.18 C102.2 68.92,47.92 69.99,47.92 70.22,48.15 R29.1 ; 90.24,57.94 90.56,58.26 C14.2 ; v1(65.66,52.06) 65.12,52.6 C42.2 ; 116.14,101.48 J23.13 ; J23.13 117.2,102.53 ; J23.13 115.08,102.53 ; J23.13 116.14,103.59 ; C212.1 v1(26.83,9.92) ; J7.7 54.09,2.18 ; J7.7 53.09,3.48 ; J7.7 52.08,2.18 ; J7.7 53.09,0.87 ; v1(84.77,58.34) U3.2 v1(86.95,58.34) ; C115.2 v1(51.9,78.67) ; v1(41.55,11.25) U9.2 v1(41.55,13.51) ; 92.06,57.18 C10.2 93.14,58 ; C81.2 v1(51.17,9.75) ; C81.2 50.65,10.44 v1(51.15,10.44) ; C81.2 50.65,9.06 v1(51.15,9.06) ; C180.2 80.53,16.24 v1(80.53,15.9) ; v1(56.44,53.6) 56.44,53.47 R22.1 ; C165.2 v1(115.2,39.58) ; C178.1 94.39,14.81 v1(94.37,14.83) ; C78.2 v1(56.64,41.68) ; R199.1 v1(115.19,40.56) ; v1(53.79,45.1) 54.3,45.61 C91.2 55.53,45.61 C92.2 ; v1(55.34,69.54) 55.07,69.81 C120.2 ; v1(51.56,57.44) C204.2 52.13,57.71 v1(51.75,58.09) ; v1(77.53,84.55) U18.2 v1(75.33,84.55) ; R21.1 63.1,55.24 v1(63.1,55.71) ; C119.2 48.43,74.9 v1(49.02,74.31) ; v1(63.71,44.91) 63.4,44.6 C103.2 ; C117.2 v1(48.41,70.73) ; C63.2 v1(53.66,41.78) ; v1(79.43,11.94) 79.37,11.89 R317.2 ; v1(82.63,53.95) C17.1 v1(82,54.58) ; v1(61.09,40.55) 61.03,40.61 C77.2 ; C19.2 v1(86.36,61.32) ; C22.2 86.89,68.31 87.3,67.9 ; v1(69.17,41.88) 68.86,42.2 C98.2 68.86,42.56 C99.2 v1(70.89,42.56) ; C215.2 v1(90.18,44.3) ; v1(79.31,84.35) C151.2 v1(78.52,83.56) ; U26.2 89.9,48.43 ; v1(65.66,45.56) 65.66,45.24 R59.2 ; v1(94.32,18.72) 94.33,18.7 C177.1 ; C166.2 v1(115.2,38.61) ; C193.1 v1(23.82,10.51) ; C179.1 94.39,12.28 v1(94.38,12.3) ; v1(58.25,42.27) 58.25,42.38 57.96,42.66 C67.2 ; C16.2 v1(83.67,53.91) ; v1(63.06,52.71) 62.87,52.52 C44.2 62.22,52.52 v1(61.76,52.06) 61.39,52.43 C43.2 60.83,52.43 v1(60.46,52.06) ; C109.2 v1(15.62,12.39) ; C79.2 v1(56.64,40.77) ; C208.2 v1(89.4,44.3) ; C108.2 v1(23.82,6.5) ; C107.2 v1(27.48,6.49) ; R98.1 v1(24.73,6.52) ; C116.2 v1(50.88,78.59) ; 79.35,76.54 81.67,76.54 81.93,76.28 v1(81.93,76.12) 81.93,72.65 81.61,72.34 79.42,72.34 C210.1 78.56,73.19 75.45,73.19 v1(75.39,73.26) 75.13,73.51 v1(75.13,74.46) 75.13,75.28 75.77,75.92 v1(76.17,75.92) v1(77.97,75.92) C209.1 79.35,76.54
  BOTTOM w0.381: v1(59.62,42.35) 59.85,42.58 C74.2 60.18,42.58 C73.2 ; v1(60.63,41.14) 60.63,41.44 C76.2
  vias: v1(0.81,99.91) v1(0.81,94.83) v1(0.81,89.75) v1(0.81,84.67) v1(0.81,79.59) v1(0.81,74.51) v1(0.81,69.43) v1(0.81,64.35) v1(0.81,59.27) v1(0.81,54.19) v1(0.81,49.11) v1(0.81,38.95) v1(0.81,33.87) v1(0.8,27.84) v1(0.8,22.76) v1(0.77,13.99) v1(0.76,6.88) v1(1.95,19.23) v1(3.57,50.47) v1(3.65,10.28) v1(4.23,7.26) v1(4.38,73.62) v1(4.38,63.13) v1(4.4,43.04) v1(4.68,27.78) v1(5.01,34.31) v1(5.63,19) v1(5.8,24.29) v1(5.94,17.17) v1(5.96,59.12) v1(6.06,91.39) v1(6.09,89.43) v1(6.13,7.83) v1(6.11,0.77) v1(6.18,53.25) v1(6.28,104.21) v1(6.45,70.79) v1(6.73,92.57) v1(6.75,88.04) v1(6.67,80.73) v1(7.12,65.39) v1(7.17,3.95) v1(7.26,47.69) v1(7.74,56.05) v1(7.7,35.7) v1(7.81,17.2) v1(7.84,14.39) v1(7.88,19.26) v1(8.01,26.91) v1(8.02,22.99) v1(8.27,86.61) v1(8.3,84.75) v1(8.36,87.99) v1(8.45,12.83) v1(8.45,92.54) v1(8.59,96.76) v1(8.93,91.24) v1(9,89.61) v1(9.42,2.15) v1(9.5,84.18) v1(9.47,75.63) v1(9.5,14.74) v1(9.74,42.13) v1(9.79,87.07) v1(9.76,10.38) v1(9.99,29.12) v1(10.11,4.19) v1(10.17,33.36) v1(11.19,0.77) v1(11.36,104.21) v1(11.51,87.03) v1(11.6,84.08) v1(11.9,55.61) v1(12.01,65.02) v1(12.06,22.28) v1(12.23,59.85) v1(12.26,6.75) v1(12.41,17.22) v1(12.45,2.75) v1(12.73,84.79) v1(12.85,86.42) v1(13,14.18) v1(13.24,62.5) v1(13.3,37.57) v1(13.36,12.7) v1(13.8,18.77) v1(13.91,10.43) v1(14.13,34.36) v1(14.32,81.12) v1(14.31,60.71) v1(14.42,50.5) v1(14.53,26.21) v1(14.75,54.87) v1(14.85,66.51) v1(15.31,58.35) v1(15.7,41.57) v1(15.8,44.84) v1(15.77,10.43) v1(15.93,68.09) v1(16.03,30.76) v1(15.98,18.89) v1(16.15,2.47) v1(16.34,49.83) v1(16.27,0.77) v1(16.44,104.21) v1(16.38,83.07) v1(16.83,57.33) v1(16.82,18) v1(16.94,70.16) v1(17.03,96.95) v1(17.06,22.12) v1(17.21,91.26) v1(17.19,64.63) v1(17.32,5.36) v1(17.44,53.61) v1(18.12,9.68) v1(18.29,71.26) v1(18.32,13.4) v1(18.54,41.58) v1(18.54,37.59) v1(18.56,63.22) v1(18.57,43.81) v1(18.58,39.13) v1(18.59,34.16) v1(18.75,67.86) v1(18.7,42.6) v1(18.67,40.68) v1(18.66,35.55) v1(18.69,32.58) v1(18.71,31.07) v1(18.75,15.69) v1(18.77,24.95) v1(18.79,2.44) v1(18.96,60.27) v1(19.26,21.47) v1(19.39,56.78) v1(19.73,60.62) v1(19.81,12.32) v1(19.89,9.59) v1(20.35,49.31) v1(20.71,86.73) v1(20.66,27.12) v1(20.81,5.33) v1(20.86,59.14) v1(21.03,88.01) v1(20.98,39.06) v1(21.01,31.45) v1(21.09,64.18) v1(21.24,94.32) v1(21.18,43.79) v1(21.22,34.07) v1(21.23,32.59) v1(21.42,24.3) v1(21.35,0.77) v1(21.52,104.21) v1(21.52,84.79) v1(21.7,52.68) v1(21.72,20.67) v1(21.81,91.31) v1(21.84,30.57) v1(21.75,17.07) v1(21.95,67.71) v1(21.86,45.54) v1(21.94,42.57) v1(21.85,25.17) v1(21.85,18.61) v1(22.03,96.92) v1(21.98,56.73) v1(22,14.47) v1(22.09,36.56) v1(22.22,46.62) v1(22.34,88.09) v1(22.3,74.56) v1(22.42,2.64) v1(22.91,28.01) v1(23.29,54.69) v1(23.3,39.05) v1(23.41,16.05) v1(23.55,43.95) v1(23.57,49.77) v1(23.93,41.99) v1(23.96,66.51) v1(24.61,77.51) v1(24.77,30.94) v1(24.93,29.62) v1(24.97,5.07) v1(25.06,48.5) v1(25.17,73.33) v1(25.2,58.97) v1(25.15,53.15) v1(25.33,45.63) v1(25.5,32.36) v1(25.58,68.32) v1(25.74,76.66) v1(25.75,36.76) v1(26.25,78.65) v1(26.41,71.56) v1(26.43,0.77) v1(26.6,104.21) v1(26.63,56.96) v1(26.59,52.35) v1(26.77,69.53) v1(26.91,47.32) v1(27.06,44.25) v1(27.22,29.1) v1(27.23,12.24) v1(27.73,95.15) v1(27.79,46.78) v1(27.98,71.43) v1(28.02,56.02) v1(28.14,51.18) v1(28.33,72.94) v1(28.42,39.63) v1(28.5,20.83) v1(28.64,4.94) v1(28.65,89.54) v1(28.67,81.97) v1(28.68,57.95) v1(28.67,27.63) v1(28.73,23.31) v1(28.79,86.99) v1(29.06,36.07) v1(29.18,25.84) v1(29.31,14.25) v1(29.5,55.05) v1(29.89,64.55) v1(29.95,52.93) v1(29.99,91.04) v1(30.06,40.93) v1(30.06,19.32) v1(30.17,37.63) v1(30.27,10.17) v1(30.52,63.9) v1(31.34,90.75) v1(31.39,21.09) v1(31.52,56.98) v1(31.51,0.77) v1(31.68,104.21) v1(31.69,59.86) v1(31.76,11.62) v1(31.84,5.72) v1(32.44,69.18) v1(32.38,55.4) v1(32.57,46.57) v1(32.72,88.99) v1(32.72,85.18) v1(32.87,93.47) v1(32.94,57.93) v1(33.08,101.48) v1(33.11,62.61) v1(33.09,29.14) v1(33.15,78.59) v1(33.16,25.8) v1(33.24,23.5) v1(33.31,71.07) v1(33.39,39.66) v1(33.43,7.94) v1(33.41,2.51) v1(33.81,93.17) v1(33.91,95.98) v1(33.92,95.08) v1(33.93,31.76) v1(33.95,94.14) v1(34.07,100.8) v1(34.1,99.86) v1(34.13,17.31) v1(34.29,30.51) v1(34.31,9.2) v1(34.64,27.63) v1(34.66,99.22) v1(34.67,98.32) v1(34.7,97.38) v1(34.99,64.43) v1(35.06,4.45) v1(35.64,62.48) v1(35.73,56.99) v1(35.77,74.5) v1(35.8,58.06) v1(35.91,56.13) v1(36.05,88.99) v1(36.24,19.99) v1(36.76,104.21) v1(36.84,59.83) v1(37.01,16.52) v1(37.01,7.74) v1(37.12,10.79) v1(37.1,2.51) v1(37.32,73.33) v1(37.25,61.68) v1(37.33,0.83) v1(37.42,81.7) v1(37.37,31.61) v1(37.69,29.55) v1(37.92,50) v1(38.06,51.51) v1(38.09,25.58) v1(38.23,69.43) v1(38.34,99.72) v1(38.44,35.82) v1(38.55,66.38) v1(38.9,58.54) v1(39.08,19.87) v1(39.21,4.54) v1(39.35,95.76) v1(39.34,5.58) v1(39.44,50.87) v1(39.41,48.99) v1(39.62,47.03) v1(39.55,29.27) v1(39.63,2.16) v1(39.69,26.06) v1(39.85,3.87) v1(39.99,33.94) v1(40.09,56.94) v1(40.14,32.11) v1(40.23,67.81) v1(40.2,64.43) v1(40.17,54.04) v1(40.25,40.76) v1(40.41,43.15) v1(40.44,27.46) v1(40.55,65.69) v1(40.48,45.71) v1(40.47,23.77) v1(40.51,18.2) v1(40.79,48.45) v1(40.95,3.87) v1(41.11,78.13) v1(41.18,40.33) v1(41.21,38.17) v1(41.42,56.11) v1(41.47,59.86) v1(41.52,9.48) v1(41.64,4.73) v1(41.72,43.13) v1(41.84,104.21) v1(41.82,49.12) v1(41.76,45.7) v1(42.04,17.68) v1(42.07,39.87) v1(42.13,22.93) v1(42.36,75.8) v1(42.36,32.1) v1(42.41,0.83) v1(42.54,85.17) v1(42.55,5.38) v1(42.74,73.27) v1(42.69,56.38) v1(42.8,36.69) v1(42.93,34.76) v1(42.98,57.58) v1(43,50.11) v1(43.21,70.47) v1(43.21,16.31) v1(43.27,48.52) v1(43.3,4.75) v1(43.5,61.63) v1(43.6,64.44) v1(43.64,2.17) v1(43.7,60.44) v1(43.76,89.02) v1(43.82,45.74) v1(44.03,28.92) v1(44.08,31.07) v1(44.07,5.3) v1(44.25,63.02) v1(44.4,58.71) v1(44.44,25.87) v1(44.43,16.28) v1(44.48,43.78) v1(44.6,40.73) v1(44.74,42.75) v1(44.83,81.48) v1(44.82,53.15) v1(44.81,34.63) v1(45.31,72.62) v1(45.3,69.67) v1(45.34,37.2) v1(45.54,75.38) v1(45.62,59.93) v1(45.58,28.55) v1(45.72,56.44) v1(45.67,54.9) v1(45.75,53.38) v1(45.7,45.71) v1(45.75,99.54) v1(45.75,43.17) v1(46.24,21.41) v1(46.24,16.33) v1(46.32,40.47) v1(46.39,67.72) v1(46.49,27.88) v1(46.54,18.27) v1(46.92,104.21) v1(46.94,95.7) v1(47.03,68.76) v1(47.55,23.63) v1(47.49,0.83) v1(47.61,78.01) v1(47.64,56.09) v1(47.65,43.92) v1(47.63,39.56) v1(47.62,37.33) v1(47.62,34.39) v1(47.56,30.76) v1(47.64,18.02) v1(47.62,3.91) v1(47.71,71.08) v1(47.66,52.9) v1(47.73,50.2) v1(47.65,46.38) v1(47.65,41.75) v1(48.09,89.02) v1(48.24,66.96) v1(48.22,36.46) v1(48.18,13.05) v1(48.47,25.85) v1(48.51,20.46) v1(48.49,16.22) v1(48.9,65.59) v1(48.91,50.29) v1(48.91,42.9) v1(48.94,40.93) v1(49.03,45.31) v1(49.02,38.6) v1(49.1,33.82) v1(49.16,85.33) v1(49.21,54.8) v1(49.43,60.7) v1(49.72,50.85) v1(49.71,33.08) v1(49.71,16.37) v1(49.8,52.36) v1(49.76,30.21) v1(49.75,24.52) v1(49.95,12.98) v1(49.96,5.92) v1(50.6,66.81) v1(50.62,7.31) v1(50.75,32.13) v1(50.94,18.86) v1(50.96,81.03) v1(51.11,44.98) v1(51.1,37.79) v1(51.23,43.19) v1(51.28,73.14) v1(51.32,28.49) v1(51.32,21.41) v1(51.29,16.71) v1(51.27,3.94) v1(51.37,40.04) v1(51.42,25.62) v1(51.54,91.9) v1(51.48,61.84) v1(51.51,6.08) v1(51.51,0.87) v1(51.63,104.27) v1(52.04,19.74) v1(52.25,37) v1(52.29,87.31) v1(52.28,30.73) v1(52.41,101.29) v1(52.36,84.2) v1(52.49,99.15) v1(52.83,77.68) v1(52.8,23.33) v1(52.82,12.22) v1(52.95,66.97) v1(52.86,45.08) v1(53.08,17.52) v1(53.41,74.19) v1(53.42,73.07) v1(53.39,69.57) v1(53.36,65.69) v1(53.51,58.81) v1(53.49,20.89) v1(53.93,101.39) v1(53.98,99.38) v1(54.13,79.51) v1(54.05,38.89) v1(54.21,24.11) v1(54.28,40.78) v1(54.32,33.07) v1(54.44,71.85) v1(54.36,28.28) v1(54.37,19.32) v1(54.56,61.88) v1(54.62,41.93) v1(54.72,36.28) v1(54.65,2.7) v1(54.97,77.5) v1(55.01,75.6) v1(55.05,59.2) v1(55.02,16.38) v1(55.11,57.05) v1(55.34,72.19) v1(55.25,51.16) v1(55.27,31.93) v1(55.29,4.08) v1(55.42,14.67) v1(55.51,40.49) v1(55.46,20.31) v1(55.56,41.95) v1(55.8,61.86) v1(55.88,65.61) v1(56.05,82.7) v1(55.97,51.38) v1(56.08,79.7) v1(56.06,76.23) v1(56.11,32.27) v1(56.13,27.86) v1(56.24,59.22) v1(56.29,93.68) v1(56.33,67.81) v1(56.33,35.4) v1(56.4,97.06) v1(56.43,51.97) v1(56.5,55.42) v1(56.47,17.61) v1(56.59,0.87) v1(56.87,74.01) v1(56.86,72.33) v1(56.99,79.12) v1(56.98,28.58) v1(57.08,104.21) v1(57.13,56.23) v1(57.21,65.57) v1(57.21,32.99) v1(57.26,20.87) v1(57.43,59.2) v1(57.53,16.66) v1(57.73,69.64) v1(57.67,6.08) v1(57.83,88.97) v1(57.77,74.39) v1(57.76,66.31) v1(57.84,19.48) v1(57.85,102.58) v1(57.92,78.49) v1(58.01,76.66) v1(57.97,38.62) v1(58.34,61.81) v1(58.33,57.37) v1(58.35,4.07) v1(58.53,74.6) v1(58.52,70.92) v1(58.53,67.97) v1(58.52,32.98) v1(58.67,56.22) v1(58.69,34.56) v1(58.82,90.89) v1(58.76,65.63) v1(58.81,59.21) v1(58.75,11.78) v1(58.96,31.84) v1(58.96,30.15) v1(59.01,17.62) v1(58.99,16.12) v1(59.22,37.67) v1(59.34,72.05) v1(59.32,69.33) v1(59.42,66.05) v1(59.69,6.32) v1(59.73,2.7) v1(60.13,74.38) v1(60.1,34.62) v1(60.13,28.69) v1(60.09,19.66) v1(60.14,18.88) v1(60.05,14.67) v1(60.22,66.46) v1(60.19,32.8) v1(60.28,36) v1(60.37,76.81) v1(60.65,70.74) v1(60.97,104.27) v1(61.04,88.91) v1(61.03,59.13) v1(61.05,73.56) v1(61.11,68.53) v1(61.14,66.19) v1(61.09,56.2) v1(61.1,54.89) v1(61.09,37.82) v1(61.09,36.44) v1(61.11,32.93) v1(61.05,8.04) v1(61.19,6.85) v1(61.33,34.64) v1(61.35,30.22) v1(61.48,24.11) v1(61.51,18.42) v1(61.67,0.87) v1(61.82,101.59) v1(61.84,99.59) v1(61.94,70.06) v1(61.91,15.49) v1(61.99,82.98) v1(61.99,82.18) v1(61.99,81.38) v1(61.99,80.58) v1(61.99,79.78) v1(62.13,20.91) v1(62.31,19.44) v1(62.32,16.94) v1(62.41,44.98) v1(62.48,74.25) v1(62.56,12.52) v1(62.56,11.52) v1(62.56,10.52) v1(62.7,69.07) v1(62.79,82.98) v1(62.79,82.18) v1(62.79,81.38) v1(62.79,80.58) v1(62.79,79.78) v1(62.79,24.17) v1(63.02,59.26) v1(63.06,61.65) v1(63.05,57.98) v1(63.22,18.51) v1(63.34,88.84) v1(63.33,73.19) v1(63.27,38.58) v1(63.42,101.67) v1(63.44,99.43) v1(63.59,82.98) v1(63.59,82.18) v1(63.59,81.38) v1(63.59,80.58) v1(63.59,79.78) v1(63.56,12.52) v1(63.56,11.52) v1(63.56,10.52) v1(63.7,26.27) v1(63.75,25.28) v1(63.76,37.96) v1(63.78,34.8) v1(63.77,33.07) v1(63.92,73.46) v1(64.03,30.41) v1(64.39,82.98) v1(64.39,82.18) v1(64.39,81.38) v1(64.39,80.58) v1(64.39,79.78) v1(64.55,64.24) v1(64.56,12.52) v1(64.56,11.52) v1(64.56,10.52) v1(64.73,73.1) v1(64.79,67.53) v1(64.79,36.61) v1(64.78,34.59) v1(64.79,32.74) v1(64.79,31.43) v1(64.82,5.36) v1(64.81,2.7) v1(65.1,61.63) v1(65.06,59.34) v1(65.17,89.07) v1(65.19,82.98) v1(65.19,82.18) v1(65.19,81.38) v1(65.19,80.58) v1(65.19,79.78) v1(65.18,70.21) v1(65.54,57.94) v1(65.62,71.91) v1(65.58,55.87) v1(65.55,54.54) v1(65.88,36.59) v1(65.88,34.65) v1(65.88,32.77) v1(65.88,31.62) v1(66.05,61.62) v1(66.05,5.43) v1(66.07,87.03) v1(66.15,67.27) v1(66.14,9.09) v1(66.17,28.19) v1(66.16,7.29) v1(66.28,77.45) v1(66.57,45.72) v1(66.9,46.91) v1(67.03,95.23) v1(67.01,62.38) v1(67.04,37.84) v1(67.03,36.65) v1(67.09,61.62) v1(67.06,32.31) v1(67.06,0.98) v1(67.24,104.21) v1(67.16,73.51) v1(67.24,68.7) v1(67.29,5.34) v1(67.52,17.01) v1(67.68,67.65) v1(67.83,37.46) v1(67.82,36.63) v1(67.82,34.67) v1(67.82,32.76) v1(67.77,30.74) v1(67.86,78.64) v1(68.01,99.94) v1(68.01,9.03) v1(68.07,19.35) v1(68.12,11.14) v1(68.19,91.3) v1(68.33,61.62) v1(68.48,31.47) v1(68.5,18.25) v1(68.45,6.23) v1(68.74,103.24) v1(68.72,63.14) v1(69.04,29.55) v1(69.04,25.41) v1(68.98,19.74) v1(69.31,88.43) v1(69.34,18.41) v1(69.38,74.83) v1(69.48,70.71) v1(69.67,67.17) v1(69.67,64.15) v1(69.72,9.48) v1(69.78,39.57) v1(69.92,40.17) v1(69.9,33.54) v1(70.05,69.36) v1(70.04,41.89) v1(69.98,23.06) v1(70.09,51.51) v1(70.21,96.94) v1(70.18,53.67) v1(70.17,19.01) v1(70.26,21) v1(70.44,29.53) v1(70.53,84.5) v1(70.67,76.32) v1(70.69,46.51) v1(70.78,63.97) v1(70.8,33.7) v1(70.81,2.74) v1(70.9,32.37) v1(70.97,40.14) v1(71.15,7.46) v1(71.27,43.67) v1(71.35,46.43) v1(71.44,34.71) v1(71.45,27.11) v1(71.55,70.53) v1(71.57,66.72) v1(71.6,13.4) v1(71.8,83.04) v1(71.91,33.75) v1(71.87,31.38) v1(72.03,68.69) v1(72.04,46.4) v1(72.12,22.15) v1(72.06,20.93) v1(72.14,0.98) v1(72.19,76.18) v1(72.18,29.78) v1(72.16,5.13) v1(72.32,104.21) v1(72.63,103.34) v1(72.63,27.36) v1(72.7,80.3) v1(72.8,72.32) v1(72.8,37.91) v1(72.88,40.61) v1(73.04,82.76) v1(73.01,38.91) v1(73.09,41.98) v1(73.16,67.13) v1(73.24,47.36) v1(73.16,25.38) v1(73.34,53.56) v1(73.32,31.94) v1(73.33,9.42) v1(73.51,34.85) v1(73.54,5.08) v1(73.62,17.14) v1(73.62,12.77) v1(73.91,69.47) v1(73.97,61.16) v1(74.4,14.79) v1(74.43,11.77) v1(74.47,56.2) v1(74.47,51.62) v1(74.54,9.6) v1(74.5,7.86) v1(74.81,27.08) v1(74.91,40.13) v1(75,103.31) v1(75.25,28.57) v1(75.24,24.77) v1(75.44,36.09) v1(75.61,78.54) v1(75.67,51.64) v1(75.71,34.33) v1(75.65,9.99) v1(75.9,47.36) v1(75.86,32.46) v1(75.87,30.38) v1(75.88,22.69) v1(75.89,7.82) v1(75.89,2.74) v1(75.98,96.35) v1(75.99,41.35) v1(75.96,15.21) v1(76.1,11.66) v1(76.07,5.66) v1(76.27,63.44) v1(76.72,36.75) v1(76.73,17.7) v1(77.14,56.75) v1(77.15,24.8) v1(77.15,102.51) v1(77.23,37.82) v1(77.21,22.71) v1(77.22,0.98) v1(77.4,104.21) v1(77.35,26.49) v1(77.63,64.74) v1(78,61.34) v1(78.02,51.61) v1(78.03,33.59) v1(78.21,53.61) v1(78.23,3.17) v1(78.27,20.35) v1(78.54,71.18) v1(78.52,12.17) v1(78.58,7.97) v1(78.62,5.08) v1(78.7,34.8) v1(78.71,29.35) v1(78.67,16.63) v1(78.93,62.66) v1(79.17,39.25) v1(79.29,71.93) v1(79.37,64.91) v1(79.41,35.64) v1(79.5,46.89) v1(79.51,44.41) v1(79.47,42.3) v1(79.59,97.49) v1(79.67,33.84) v1(79.68,22.3) v1(80,84.96) v1(80.13,31.62) v1(80.07,24.14) v1(80.22,100.17) v1(80.17,18.69) v1(80.32,46.41) v1(80.33,43.19) v1(80.33,28.26) v1(80.4,58.32) v1(80.35,41.69) v1(80.51,48.32) v1(80.45,36.9) v1(80.62,92.52) v1(80.79,14) v1(80.76,9.48) v1(80.97,34.11) v1(80.97,7.82) v1(80.97,2.74) v1(81.07,96.5) v1(81.08,14.86) v1(81.16,79.46) v1(81.27,16.16) v1(81.36,60.91) v1(81.68,26.44) v1(81.82,53.68) v1(81.92,83.49) v1(81.86,68.84) v1(82.01,15.01) v1(82.12,15.99) v1(82.22,65.97) v1(82.3,0.98) v1(82.48,104.21) v1(82.47,48.25) v1(82.69,29.03) v1(82.77,75.41) v1(82.89,16.88) v1(82.88,14.77) v1(83,77.23) v1(82.95,51.63) v1(83.02,30.54) v1(82.96,16.04) v1(83.11,68.64) v1(83.1,21.14) v1(83.7,76.34) v1(84.05,42.82) v1(84.14,35.07) v1(84.25,24.09) v1(84.28,88.69) v1(84.27,71.5) v1(84.41,100.65) v1(84.39,48.29) v1(84.37,30.84) v1(84.39,27.3) v1(84.42,10.85) v1(84.51,44.51) v1(84.45,9.14) v1(84.71,57.43) v1(84.78,95.71) v1(84.76,56.25) v1(84.85,46.05) v1(84.87,60.81) v1(85.14,77.78) v1(85.12,65.74) v1(85.16,64.29) v1(85.25,26.44) v1(85.24,21.12) v1(85.38,17.69) v1(85.42,15.45) v1(85.38,6.91) v1(85.52,53.56) v1(85.45,19.66) v1(85.55,79.75) v1(85.74,16.77) v1(85.87,12.26) v1(86.2,68.84) v1(86.21,15.45) v1(86.34,74.32) v1(86.33,13.47) v1(86.42,64.4) v1(86.51,79.14) v1(86.6,26.94) v1(86.76,16.59) v1(87.13,75.28) v1(87.18,89.46) v1(87.38,66.02) v1(87.36,64.28) v1(87.38,0.98) v1(87.49,22.76) v1(87.49,10.35) v1(87.56,104.21) v1(87.64,72.04) v1(87.83,100.69) v1(87.82,56.42) v1(87.9,95.21) v1(87.87,76.9) v1(87.91,47.41) v1(87.88,2.51) v1(88,58.16) v1(87.99,51.65) v1(88.06,64.97) v1(88.15,17.36) v1(88.19,53.85) v1(88.18,26.98) v1(88.21,19.93) v1(88.44,66.02) v1(88.44,35.87) v1(88.55,12.93) v1(88.67,14.89) v1(88.9,21.95) v1(89.34,2.5) v1(89.44,83.75) v1(89.5,48.51) v1(89.5,19.28) v1(89.59,53.82) v1(89.63,16.78) v1(90.13,82.68) v1(90.36,22.05) v1(90.46,42.57) v1(90.51,5.48) v1(90.64,64.97) v1(90.6,26.2) v1(90.75,57.6) v1(90.79,13.56) v1(91.03,9.81) v1(91.13,39.86) v1(91.27,20.43) v1(91.28,15.27) v1(91.38,84) v1(91.4,57.23) v1(91.44,1.65) v1(91.65,81.67) v1(91.67,23.44) v1(91.8,47.95) v1(91.93,17.43) v1(91.97,45.95) v1(92.13,50.04) v1(92.09,11.07) v1(92.19,35.26) v1(92.39,72.23) v1(92.48,85.08) v1(92.46,0.98) v1(92.64,104.21) v1(92.7,99.14) v1(92.67,57.11) v1(92.94,31.11) v1(92.97,53.97) v1(93.16,58.43) v1(93.3,20.46) v1(93.37,51.48) v1(93.82,87.93) v1(93.9,5.75) v1(93.98,75.31) v1(94.32,16.8) v1(94.36,49.88) v1(94.94,91.13) v1(94.96,65.46) v1(95,61.11) v1(95.08,78.03) v1(95.09,68.8) v1(95.06,44.84) v1(95.39,42.63) v1(95.58,22.77) v1(95.68,26.2) v1(95.76,7.58) v1(95.91,83.02) v1(95.85,39.86) v1(96.02,81.33) v1(96.02,10.22) v1(96.05,29.23) v1(96.21,20.87) v1(96.45,65.37) v1(96.39,60.16) v1(96.51,72.41) v1(96.54,54.52) v1(96.57,96.27) v1(96.78,74.35) v1(97.13,69.26) v1(97.54,0.98) v1(97.72,104.21) v1(97.76,99.2) v1(97.85,93.03) v1(98.14,70.77) v1(98.5,34.89) v1(98.97,103.39) v1(98.96,72.96) v1(99.02,66.47) v1(99.02,62.57) v1(99.13,68.99) v1(99.1,40.48) v1(99.24,6.36) v1(99.27,36.48) v1(99.38,43.83) v1(99.45,54.29) v1(99.65,88.33) v1(99.74,57.73) v1(99.79,65.86) v1(99.79,59.91) v1(99.78,25.33) v1(99.94,42.05) v1(100.12,82.37) v1(100.06,37.98) v1(100.12,3.73) v1(100.27,91.96) v1(100.29,48.82) v1(100.3,33.08) v1(100.29,2.49) v1(100.41,90.64) v1(100.36,63.97) v1(100.38,40.98) v1(100.81,67.74) v1(100.76,26.2) v1(100.85,86.58) v1(101.15,93.23) v1(101.22,46.5) v1(101.31,78.16) v1(101.48,53.66) v1(101.66,2.2) v1(101.8,98.31) v1(101.8,95.61) v1(101.98,70.05) v1(101.98,29.14) v1(102.25,91.8) v1(102.37,101.16) v1(102.46,97.58) v1(102.6,67.64) v1(102.61,35.26) v1(102.62,0.98) v1(102.8,104.21) v1(102.85,2.66) v1(102.93,96.37) v1(102.9,62.69) v1(102.89,33.02) v1(102.89,4.73) v1(103.02,85.74) v1(103.13,72.34) v1(103.23,60.13) v1(103.31,55.62) v1(103.48,49.98) v1(103.56,48.63) v1(103.71,91.89) v1(103.8,69.16) v1(103.8,68.36) v1(103.8,66.51) v1(103.97,37.75) v1(104.15,98.58) v1(104.18,75.27) v1(104.16,40.93) v1(104.18,39.58) v1(104.3,42.05) v1(104.41,35.39) v1(104.62,93.13) v1(104.6,69.16) v1(104.6,68.36) v1(104.6,65.07) v1(104.6,60.37) v1(104.57,2.81) v1(105.05,57.09) v1(105.2,82.37) v1(105.38,51.44) v1(105.37,43.95) v1(105.52,66.69) v1(105.6,50.08) v1(105.67,30.74) v1(105.84,26.2) v1(105.87,37.81) v1(106.05,2.78) v1(106.39,95.72) v1(106.39,78.16) v1(106.41,62.63) v1(106.38,60.74) v1(106.46,101.34) v1(106.56,53.66) v1(106.57,46.68) v1(106.69,86.85) v1(106.84,59.82) v1(106.91,98.93) v1(107,91.95) v1(106.99,4.9) v1(106.96,3.07) v1(107.17,83.35) v1(107.46,85.76) v1(107.54,74.22) v1(107.67,49.4) v1(107.7,0.98) v1(107.79,55.51) v1(107.88,104.21) v1(107.92,32.18) v1(108,98.3) v1(108.08,40.43) v1(108.24,57.8) v1(108.2,45.8) v1(108.5,65.89) v1(108.63,28.67) v1(108.7,84.55) v1(108.72,42.54) v1(108.69,39.18) v1(108.83,72.42) v1(108.93,60.05) v1(109.06,101.24) v1(109.22,49.07) v1(109.35,93.22) v1(109.47,98.87) v1(109.53,96.82) v1(110.18,56.53) v1(110.28,82.37) v1(110.35,2.63) v1(110.44,87.65) v1(110.46,51.44) v1(110.61,98.73) v1(110.57,96.26) v1(110.65,77.28) v1(110.55,73.21) v1(110.7,75.19) v1(110.81,79.32) v1(110.86,86.53) v1(110.92,26.2) v1(111.01,81.35) v1(111.01,63.74) v1(110.96,60.3) v1(110.97,53.9) v1(111.38,83.4) v1(111.5,101.23) v1(111.82,98.76) v1(111.78,95.63) v1(112.52,31.61) v1(112.78,0.98) v1(112.89,71.25) v1(112.93,4.99) v1(112.96,104.21) v1(113.03,43) v1(113.08,55.6) v1(113.43,98.5) v1(113.52,94.6) v1(113.57,101.24) v1(113.68,49.76) v1(114.46,69.58) v1(115.07,77.37) v1(115.09,28.7) v1(115.24,90.54) v1(115.24,80.78) v1(115.24,75.41) v1(115.29,98.58) v1(115.29,94.93) v1(115.32,88.33) v1(115.41,83.84) v1(115.41,78.17) v1(115.7,82.25) v1(115.72,56.85) v1(115.67,47.85) v1(115.77,91.87) v1(115.92,53.9) v1(116.02,74.91) v1(116,26.2) v1(116.2,78.43) v1(116.36,36.32) v1(116.49,62.65) v1(116.59,65.19) v1(116.82,92.97) v1(116.78,33.41) v1(117.18,98.44) v1(117.32,2.61) v1(117.41,101.29) v1(117.44,61.9) v1(117.5,58.91) v1(117.61,63.9) v1(117.72,102.95) v1(117.81,32.12) v1(117.87,42.04) v1(117.86,0.98) v1(118.04,104.21) v1(118.22,51.16) v1(118.67,49.77) v1(118.74,46.02) v1(118.7,5.69) v1(118.89,61.73) v1(119.01,58.94) v1(119.11,25.73) v1(119.24,68.19) v1(119.35,60.55) v1(119.3,34.46) v1(119.52,92.54) v1(119.49,65.5) v1(119.6,98.35) v1(119.58,94.41) v1(119.57,91.23) v1(119.6,89.87) v1(119.98,62.55) v1(120.67,28.03) v1(121.13,73.08) v1(121.41,39.95) v1(121.73,89.36) v1(121.74,25.9) v1(121.8,85.3) v1(121.93,101.51) v1(121.99,81.38) v1(122.18,94.58) v1(123.26,66.84) v1(124.15,58.22) v1(124.15,53.14) v1(124.15,48.06) v1(124.15,42.98) v1(124.15,37.9) v1(124.15,32.82) v1(124.15,27.74) v1(124.21,98.57) v1(124.21,93.49) v1(124.21,88.41) v1(124.21,83.33) v1(124.21,78.25) v1(124.21,71.36)
